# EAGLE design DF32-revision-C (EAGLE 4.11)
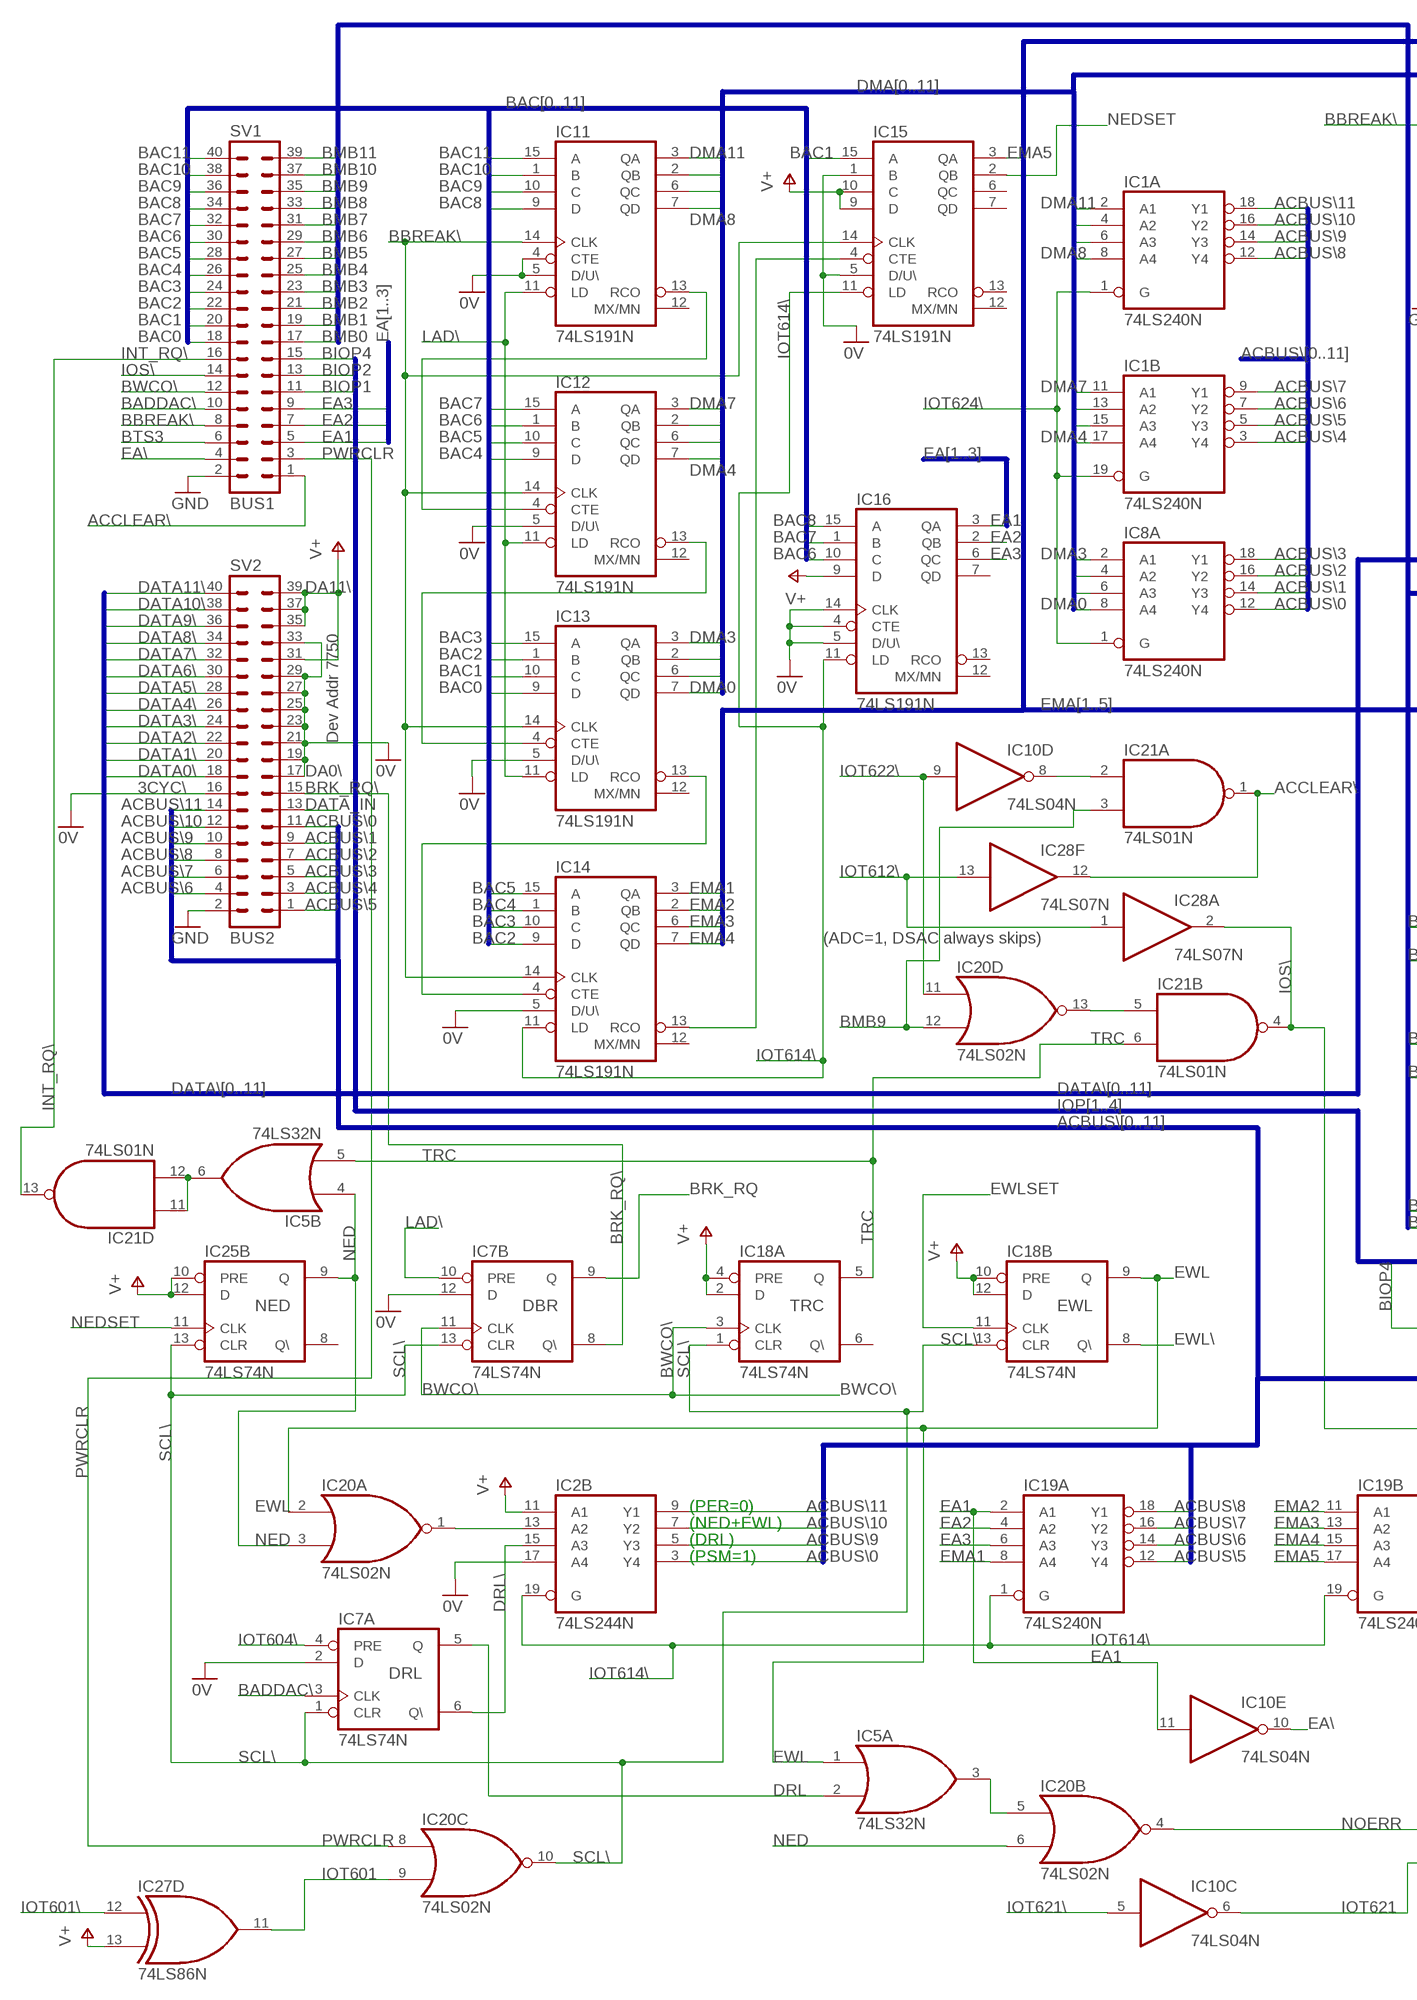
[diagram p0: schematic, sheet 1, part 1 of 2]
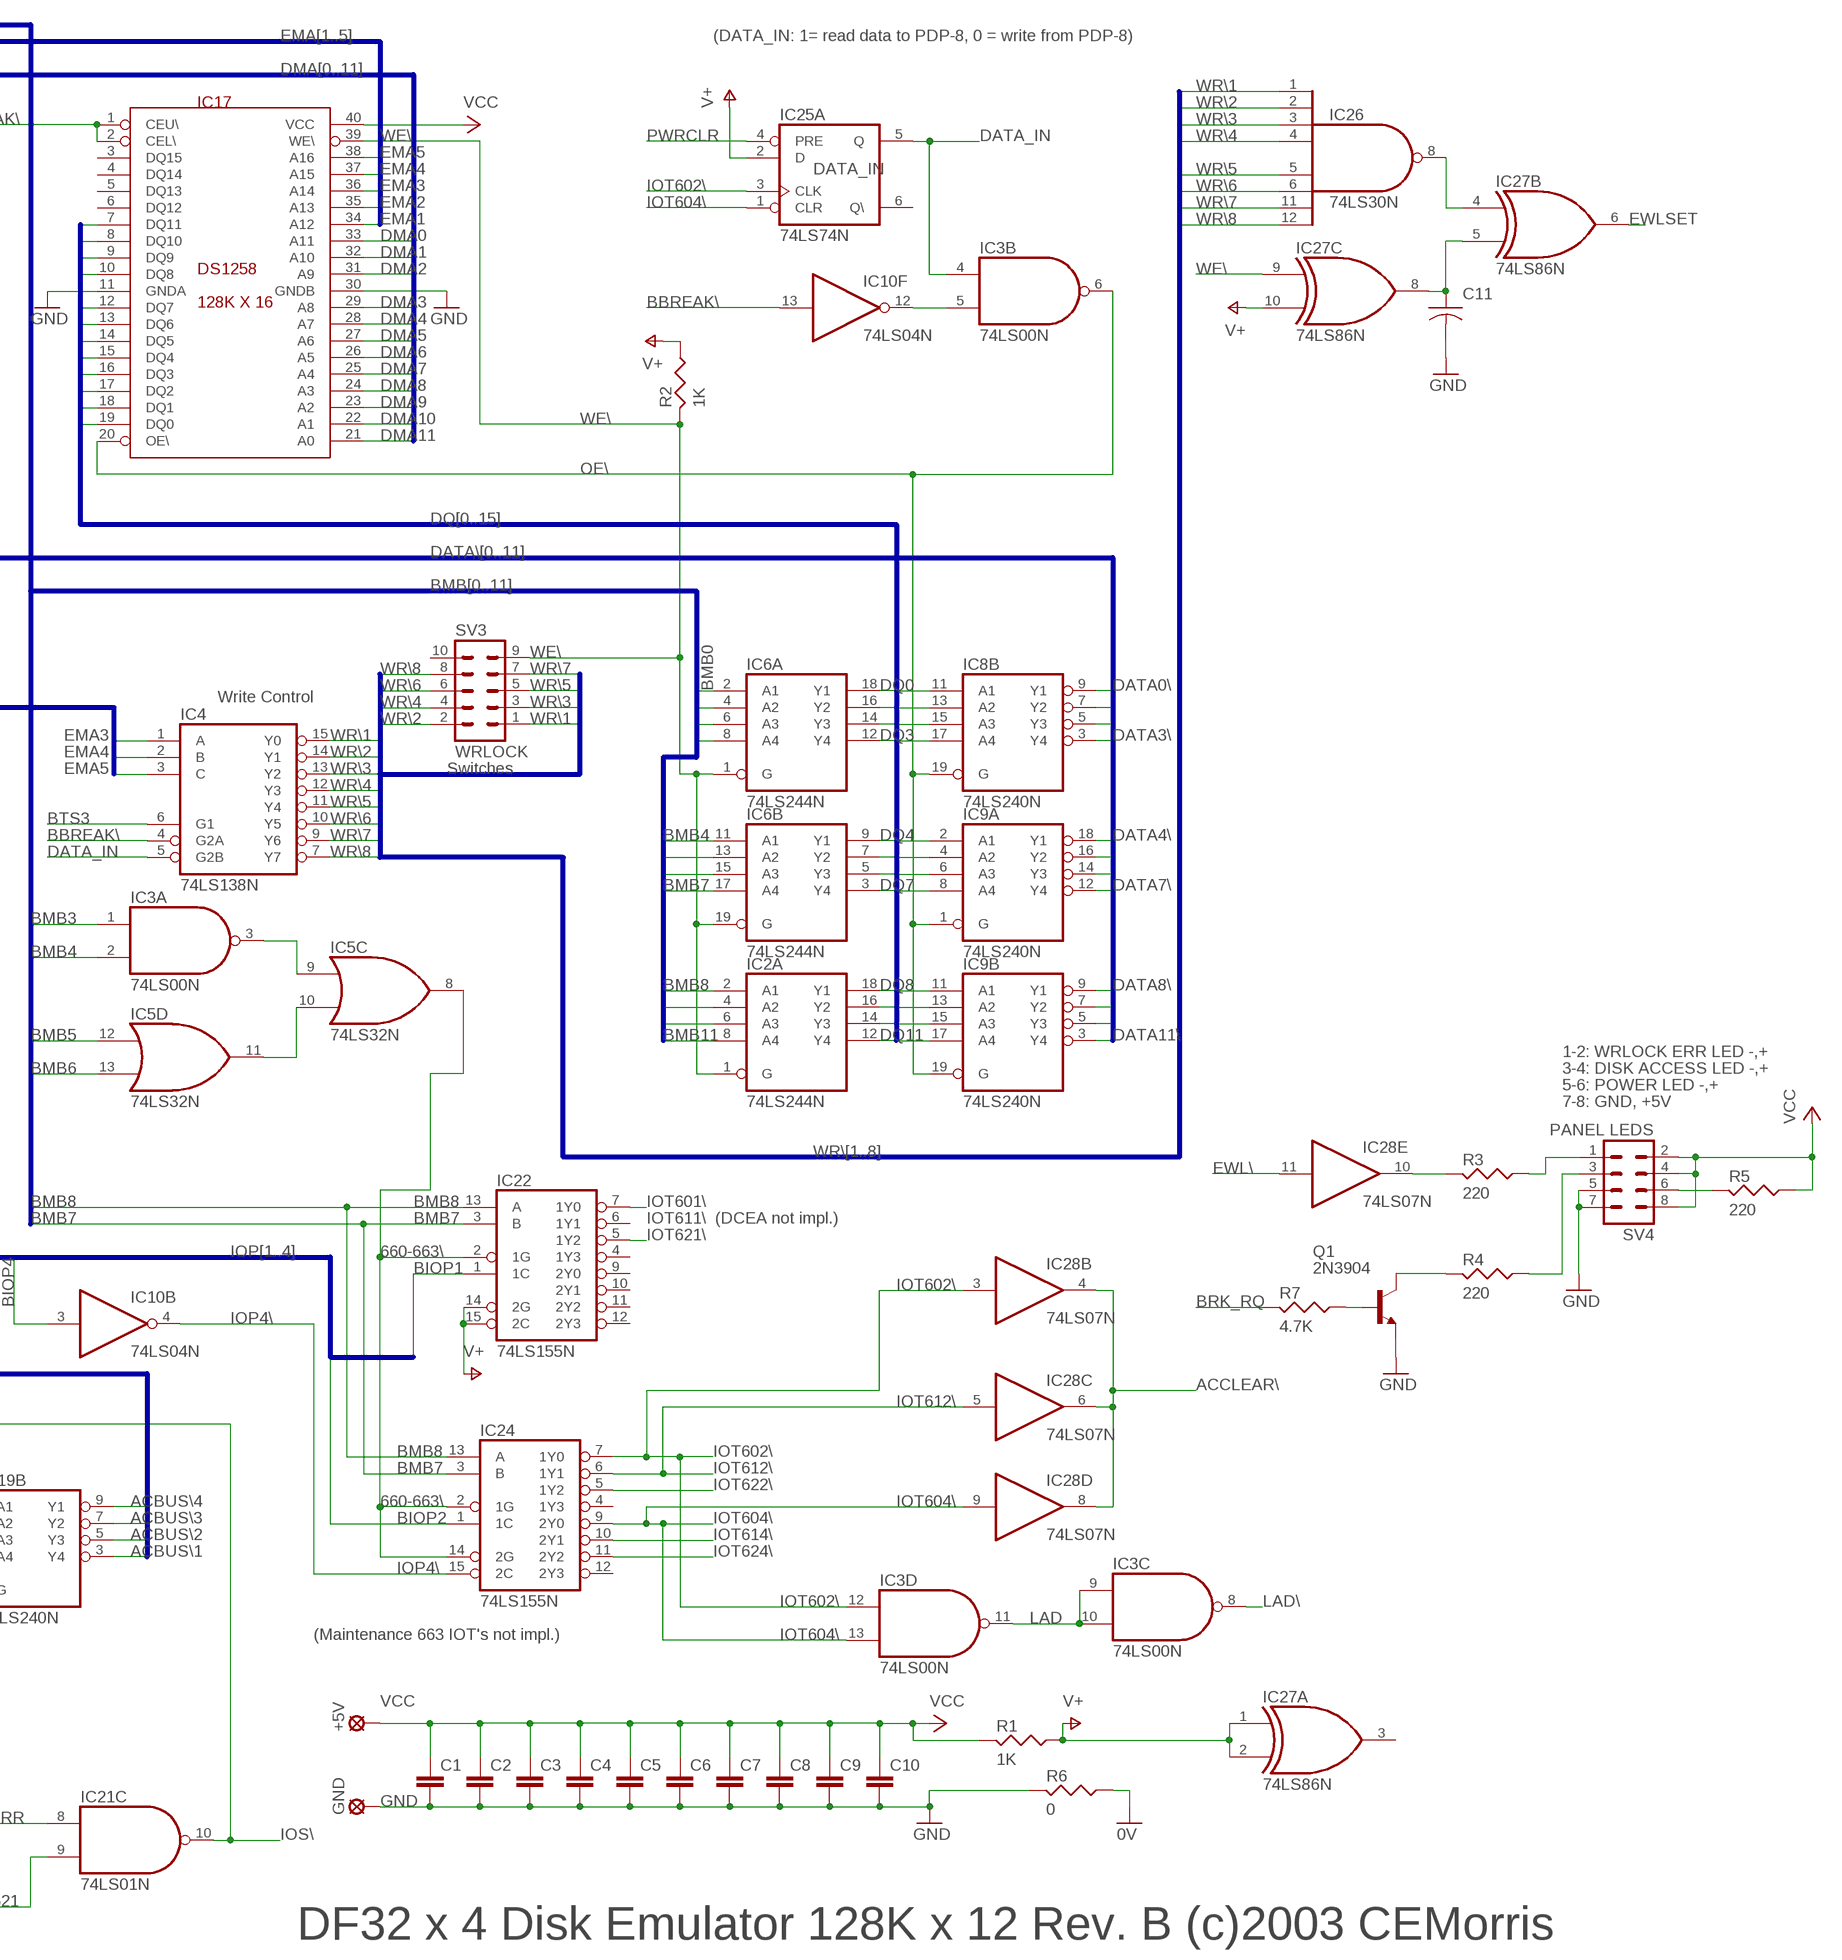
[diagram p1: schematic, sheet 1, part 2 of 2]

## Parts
+5V  SE14  [SE14]
C1  C5/3.5  [C5B3.5]
C2  C5/3.5  [C5B3.5]
C3  C5/3.5  [C5B3.5]
C4  C5/3.5  [C5B3.5]
C5  C5/3.5  [C5B3.5]
C6  C5/3.5  [C5B3.5]
C7  C5/3.5  [C5B3.5]
C8  C5/3.5  [C5B3.5]
C9  C5/3.5  [C5B3.5]
C10  C5/3.5  [C5B3.5]
C11  CAP-2,5  [C-2,5]
GND  SE14  [SE14]
IC1  74LS240N  [DIL20]
IC2  74LS244N  [DIL20]
IC3  74LS00N  [DIL14]
IC4  74LS138N  [DIL16]
IC5  74LS32N  [DIL14]
IC6  74LS244N  [DIL20]
IC7  74LS74N  [DIL14]
IC8  74LS240N  [DIL20]
IC9  74LS240N  [DIL20]
IC10  74LS04N  [DIL14]
IC11  74LS191N  74LS190N  [DIL16]
IC12  74LS191N  74LS190N  [DIL16]
IC13  74LS191N  74LS190N  [DIL16]
IC14  74LS191N  74LS190N  [DIL16]
IC15  74LS191N  74LS190N  [DIL16]
IC16  74LS191N  74LS190N  [DIL16]
IC17  DS1258  [DIL40]
IC18  74LS74N  [DIL14]
IC19  74LS240N  [DIL20]
IC20  74LS02N  [DIL14]
IC21  74LS01N  [DIL14]
IC22  74LS155N  [DIL16]
IC24  74LS155N  [DIL16]
IC25  74LS74N  [DIL14]
IC26  74LS30N  [DIL14]
IC27  74LS86N  [DIL14]
IC28  74LS07N  [DIL14]
Q1  2N3904  [TO92]
R1  1K  RESUS-5  [R-5]
R2  1K  RESUS-7,5  [R-7,5]
R3  220  RESUS-5  [R-5]
R4  220  RESUS-5  [R-5]
R5  220  RESUS-5  [R-5]
R6  0  RESUS-5  [R-5]
R7  4.7K  RESUS-5  [R-5]
SV1  BUS1  MA20-2  [MA20-2]
SV2  BUS2  MA20-2  [MA20-2]
SV3  WRLOCK  MA05-2  [MA05-2]
SV4  PANEL LEDS  MA04-2  [MA04-2]

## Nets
0V: IC2.17(B:A4) IC7.2(A:D) IC7.12(B:D) IC11.4(CTE) IC11.5(D/U\) IC12.5(D/U\) IC13.5(D/U\) IC14.5(D/U\) IC15.1(B) IC15.5(D/U\) IC16.4(CTE) IC16.5(D/U\) IC16.14(CLK) R6.1 SV2.16 SV2.17 SV2.19 SV2.21 SV2.23 SV2.25 SV2.27 SV2.29 SV2.33
660-663\: IC5.8(C:O) IC22.2(1G) IC24.2(1G) IC24.14(2G)
(NED+EWL)\: IC2.13(B:A2) IC20.1(A:O)
ACBUS\0: IC2.3(B:Y4) IC8.12(A:Y4) SV2.11
ACBUS\1: IC8.14(A:Y3) IC19.3(B:Y4) SV2.9
ACBUS\2: IC8.16(A:Y2) IC19.5(B:Y3) SV2.7
ACBUS\3: IC8.18(A:Y1) IC19.7(B:Y2) SV2.5
ACBUS\4: IC1.3(B:Y4) IC19.9(B:Y1) SV2.3
ACBUS\5: IC1.5(B:Y3) IC19.12(A:Y4) SV2.1
ACBUS\6: IC1.7(B:Y2) IC19.14(A:Y3) SV2.4
ACBUS\7: IC1.9(B:Y1) IC19.16(A:Y2) SV2.6
ACBUS\8: IC1.12(A:Y4) IC19.18(A:Y1) SV2.8
ACBUS\9: IC1.14(A:Y3) IC2.5(B:Y3) SV2.10
ACBUS\10: IC1.16(A:Y2) IC2.7(B:Y2) SV2.12
ACBUS\11: IC1.18(A:Y1) IC2.9(B:Y1) SV2.14
ACCLEAR\: IC21.1(A:O) IC28.4(B:O) IC28.6(C:O) IC28.8(D:O) IC28.12(F:O) SV1.1
BAC0: IC13.9(D) SV1.18
BAC1: IC13.10(C) IC15.15(A) SV1.20
BAC2: IC13.1(B) IC14.9(D) SV1.22
BAC3: IC13.15(A) IC14.10(C) SV1.24
BAC4: IC12.9(D) IC14.1(B) SV1.26
BAC5: IC12.10(C) IC14.15(A) SV1.28
BAC6: IC12.1(B) IC16.10(C) SV1.30
BAC7: IC12.15(A) IC16.1(B) SV1.32
BAC8: IC11.9(D) IC16.15(A) SV1.34
BAC9: IC11.10(C) SV1.36
BAC10: IC11.1(B) SV1.38
BAC11: IC11.15(A) SV1.40
BADDAC\: IC7.3(A:CLK) SV1.10
BBREAK\: IC4.4(G2A) IC10.13(F:I) IC11.14(CLK) IC12.14(CLK) IC13.14(CLK) IC14.14(CLK) IC15.14(CLK) IC17.1(CEU\) IC17.2(CEL\) SV1.8
BIOP1: IC22.1(1C) SV1.11
BIOP2: IC24.1(1C) SV1.13
BIOP4: IC10.3(B:I) SV1.15
BMB0: IC6.2(A:A1) SV1.17
BMB1: IC6.4(A:A2) SV1.19
BMB2: IC6.6(A:A3) SV1.21
BMB3: IC3.1(A:I0) IC6.8(A:A4) SV1.23
BMB4: IC3.2(A:I1) IC6.11(B:A1) SV1.25
BMB5: IC5.12(D:I0) IC6.13(B:A2) SV1.27
BMB6: IC5.13(D:I1) IC6.15(B:A3) SV1.29
BMB7: IC6.17(B:A4) IC22.3(B) IC24.3(B) SV1.31
BMB8: IC2.2(A:A1) IC22.13(A) IC24.13(A) SV1.33
BMB9: IC2.4(A:A2) IC20.12(D:I1) IC21.3(A:I1) SV1.35
BMB10: IC2.6(A:A3) SV1.37
BMB11: IC2.8(A:A4) SV1.39
BRK_RQ: IC7.9(B:Q) R7.2
BRK_RQ\: IC7.8(B:Q\) SV2.15
BTS3: IC4.6(G1) SV1.6
BWCO\: IC7.11(B:CLK) IC18.3(A:CLK) SV1.12
DATA0\: IC8.9(B:Y1) SV2.18
DATA1\: IC8.7(B:Y2) SV2.20
DATA2\: IC8.5(B:Y3) SV2.22
DATA3\: IC8.3(B:Y4) SV2.24
DATA4\: IC9.18(A:Y1) SV2.26
DATA5\: IC9.16(A:Y2) SV2.28
DATA6\: IC9.14(A:Y3) SV2.30
DATA7\: IC9.12(A:Y4) SV2.32
DATA8\: IC9.9(B:Y1) SV2.34
DATA9\: IC9.7(B:Y2) SV2.36
DATA10\: IC9.5(B:Y3) SV2.38
DATA11\: IC9.3(B:Y4) SV2.40
DATA_IN: IC3.4(B:I0) IC4.5(G2B) IC25.5(A:Q) SV2.13
DISK_LED: R4.1 SV4.3
DMA0: IC8.8(A:A4) IC13.7(QD) IC17.33(A11)
DMA1: IC8.6(A:A3) IC13.6(QC) IC17.32(A10)
DMA2: IC8.4(A:A2) IC13.2(QB) IC17.31(A9)
DMA3: IC8.2(A:A1) IC13.3(QA) IC17.29(A8)
DMA4: IC1.17(B:A4) IC12.7(QD) IC17.28(A7)
DMA5: IC1.15(B:A3) IC12.6(QC) IC17.27(A6)
DMA6: IC1.13(B:A2) IC12.2(QB) IC17.26(A5)
DMA7: IC1.11(B:A1) IC12.3(QA) IC17.25(A4)
DMA8: IC1.8(A:A4) IC11.7(QD) IC17.24(A3)
DMA9: IC1.6(A:A3) IC11.6(QC) IC17.23(A2)
DMA10: IC1.4(A:A2) IC11.2(QB) IC17.22(A1)
DMA11: IC1.2(A:A1) IC11.3(QA) IC17.21(A0)
DQ0: IC6.18(A:Y1) IC8.11(B:A1) IC17.19(DQ0)
DQ1: IC6.16(A:Y2) IC8.13(B:A2) IC17.18(DQ1)
DQ2: IC6.14(A:Y3) IC8.15(B:A3) IC17.17(DQ2)
DQ3: IC6.12(A:Y4) IC8.17(B:A4) IC17.16(DQ3)
DQ4: IC6.9(B:Y1) IC9.2(A:A1) IC17.15(DQ4)
DQ5: IC6.7(B:Y2) IC9.4(A:A2) IC17.14(DQ5)
DQ6: IC6.5(B:Y3) IC9.6(A:A3) IC17.13(DQ6)
DQ7: IC6.3(B:Y4) IC9.8(A:A4) IC17.12(DQ7)
DQ8: IC2.18(A:Y1) IC9.11(B:A1) IC17.10(DQ8)
DQ9: IC2.16(A:Y2) IC9.13(B:A2) IC17.9(DQ9)
DQ10: IC2.14(A:Y3) IC9.15(B:A3) IC17.8(DQ10)
DQ11: IC2.12(A:Y4) IC9.17(B:A4) IC17.7(DQ11)
DRL: IC5.2(A:I1) IC7.5(A:Q)
DRL\: IC2.15(B:A3) IC7.6(A:Q\)
EA1: IC10.11(E:I) IC16.3(QA) IC19.2(A:A1) SV1.5
EA2: IC16.2(QB) IC19.4(A:A2) SV1.7
EA3: IC16.6(QC) IC19.6(A:A3) SV1.9
EA\: IC10.10(E:O) SV1.4
EMA1: IC14.3(QA) IC17.34(A12) IC19.8(A:A4)
EMA2: IC14.2(QB) IC17.35(A13) IC19.11(B:A1)
EMA3: IC4.1(A) IC14.6(QC) IC17.36(A14) IC19.13(B:A2)
EMA4: IC4.2(B) IC14.7(QD) IC17.37(A15) IC19.15(B:A3)
EMA5: IC4.3(C) IC15.3(QA) IC17.38(A16) IC19.17(B:A4)
EWL: IC5.1(A:I0) IC18.9(B:Q) IC20.2(A:I0)
EWL\: IC18.8(B:Q\) IC28.11(E:I)
EWLSET: IC18.11(B:CLK) IC27.6(B:O)
GND [supply]: C1.2 C2.2 C3.2 C4.2 C5.2 C6.2 C7.2 C8.2 C9.2 C10.2 C11.2 GND.MP IC17.11(GNDA) IC17.30(GNDB) Q1.3(E) R6.2 SV1.2 SV2.2 SV4.5 SV4.7
INT_RQ\: IC21.13(D:O) SV1.16
IOP4\: IC10.4(B:O) IC24.15(2C)
IOS\: IC21.4(B:O) IC21.10(C:O) IC28.2(A:O) SV1.14
IOT601: IC20.9(C:I1) IC27.11(D:O)
IOT601\: IC22.7(1Y0) IC27.12(D:I0)
IOT602\: IC3.12(D:I0) IC24.7(1Y0) IC25.3(A:CLK) IC28.3(B:I)
IOT604\: IC3.13(D:I1) IC7.4(A:PRE) IC24.9(2Y0) IC25.1(A:CLR) IC28.9(D:I)
IOT612\: IC24.6(1Y1) IC28.1(A:I) IC28.5(C:I) IC28.13(F:I)
IOT614\: IC2.19(B:G) IC14.11(LD) IC15.11(LD) IC16.11(LD) IC19.1(A:G) IC19.19(B:G) IC24.10(2Y1)
IOT621: IC10.6(C:O) IC21.9(C:I1)
IOT621\: IC10.5(C:I) IC22.5(1Y2)
IOT622\: IC10.9(D:I) IC20.11(D:I0) IC24.5(1Y2)
IOT624\: IC1.1(A:G) IC1.19(B:G) IC8.1(A:G) IC24.11(2Y2)
LAD: IC3.9(C:I0) IC3.10(C:I1) IC3.11(D:O)
LAD\: IC3.8(C:O) IC7.10(B:PRE) IC11.11(LD) IC12.11(LD) IC13.11(LD)
N$1: C11.1 IC27.5(B:I1) IC27.8(C:O)
N$2: IC5.6(B:O) IC21.11(D:I0) IC21.12(D:I1)
N$3: IC28.10(E:O) R3.2
N$4: IC3.5(B:I1) IC10.12(F:O)
N$5: Q1.1(C) R4.2
N$6: R5.2 SV4.6
N$10: IC13.13(RCO) IC14.4(CTE)
N$11: IC12.13(RCO) IC13.4(CTE)
N$12: IC11.13(RCO) IC12.4(CTE)
N$13: IC3.3(A:O) IC5.9(C:I0)
N$14: IC14.13(RCO) IC15.4(CTE)
N$15: IC5.10(C:I1) IC5.11(D:O)
N$17: IC20.13(D:O) IC21.5(B:I0)
N$19: IC5.3(A:O) IC20.5(B:I0)
N$21: IC10.8(D:O) IC21.2(A:I0)
N$22: IC26.8(O) IC27.4(B:I0)
N$23: Q1.2(B) R7.1
NED: IC5.4(B:I0) IC20.3(A:I1) IC20.6(B:I1) IC25.9(B:Q)
NEDSET: IC15.2(QB) IC25.11(B:CLK)
NOERR: IC20.4(B:O) IC21.8(C:I0)
OE\: IC3.6(B:O) IC8.19(B:G) IC9.1(A:G) IC9.19(B:G) IC17.20(OE\)
PWRCLR: IC20.8(C:I0) IC25.4(A:PRE) SV1.3
SCL\: IC7.1(A:CLR) IC7.13(B:CLR) IC18.1(A:CLR) IC18.13(B:CLR) IC20.10(C:O) IC25.13(B:CLR)
TRC: IC5.5(B:I1) IC18.5(A:Q) IC21.6(B:I1)
V+: IC2.11(B:A1) IC15.9(D) IC15.10(C) IC16.9(D) IC18.2(A:D) IC18.4(A:PRE) IC18.10(B:PRE) IC18.12(B:D) IC22.14(2G) IC22.15(2C) IC25.2(A:D) IC25.10(B:PRE) IC25.12(B:D) IC27.1(A:I0) IC27.2(A:I1) IC27.10(C:I1) IC27.13(D:I1) R1.1 R2.1 SV2.31 SV2.35 SV2.37 SV2.39
VCC [supply]: +5V.MP C1.1 C2.1 C3.1 C4.1 C5.1 C6.1 C7.1 C8.1 C9.1 C10.1 IC17.40(VCC) R1.2 R5.1 SV4.2 SV4.4 SV4.8
WE\: IC2.1(A:G) IC6.1(A:G) IC6.19(B:G) IC17.39(WE\) IC27.9(C:I0) R2.2 SV3.9
WR\1: IC4.15(Y0) IC26.1(I0) SV3.1
WR\2: IC4.14(Y1) IC26.2(I1) SV3.2
WR\3: IC4.13(Y2) IC26.3(I2) SV3.3
WR\4: IC4.12(Y3) IC26.4(I3) SV3.4
WR\5: IC4.11(Y4) IC26.5(I4) SV3.5
WR\6: IC4.10(Y5) IC26.6(I5) SV3.6
WR\7: IC4.9(Y6) IC26.11(I6) SV3.7
WR\8: IC4.7(Y7) IC26.12(I7) SV3.8
WRITELOCK_LED: R3.1 SV4.1
Unconnected: IC10.1(A:I) IC10.2(A:O) IC11.12(MX/MN) IC12.12(MX/MN) IC13.12(MX/MN) IC14.12(MX/MN) IC15.6(QC) IC15.7(QD) IC15.12(MX/MN) IC15.13(RCO) IC16.7(QD) IC16.12(MX/MN) IC16.13(RCO) IC17.3(DQ15) IC17.4(DQ14) IC17.5(DQ13) IC17.6(DQ12) IC18.6(A:Q\) IC22.4(1Y3) IC22.6(1Y1) IC22.9(2Y0) IC22.10(2Y1) IC22.11(2Y2) IC22.12(2Y3) IC24.4(1Y3) IC24.12(2Y3) IC25.6(A:Q\) IC25.8(B:Q\) IC27.3(A:O) SV3.10

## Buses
BAC[0..11]
DATA\[0..11]
DMA[0..11]
EMA[1..5]
BMB[0..11]
EMA[3..5]
DQ[0..15]
IOP[1..4]
ACBUS\[0..11]
EA[1..3]
WR\[1..8]

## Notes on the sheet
- (DATA_IN: 1= read data to PDP-8, 0 = write from PDP-8)
- DATA_IN
- DA11\
- Write Control
- Dev Addr 7750
- DA0\ | Switches
- 3CYC\
- (ADC=1, DSAC always skips)
- 1-2: WRLOCK ERR LED -,+
- 3-4: DISK ACCESS LED -,+
- 5-6: POWER LED -,+
- 7-8: GND, +5V
- IOT611\  (DCEA not impl.)
- NED | DBR | TRC | EWL
- (PER=0)
- (NED+EWL)
- (DRL)
- (PSM=1)
- (Maintenance 663 IOT's not impl.)
- DRL
- DF32 x 4 Disk Emulator 128K x 12 Rev. B (c)2003 CEMorris

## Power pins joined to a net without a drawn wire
GND: IC1.10(P:GND) IC2.10(P:GND) IC3.7(P:GND) IC4.8(GND) IC5.7(P:GND) IC6.10(P:GND) IC7.7(P:GND) IC8.10(P:GND) IC9.10(P:GND) IC10.7(P:GND) IC11.8(GND) IC12.8(GND) IC13.8(GND) IC14.8(GND) IC15.8(GND) IC16.8(GND) IC18.7(P:GND) IC19.10(P:GND) IC20.7(P:GND) IC21.7(P:GND) IC22.8(GND) IC24.8(GND) IC25.7(P:GND) IC26.7(GND) IC27.7(P:GND) IC28.7(P:GND)
VCC: IC1.20(P:VCC) IC2.20(P:VCC) IC3.14(P:VCC) IC4.16(VCC) IC5.14(P:VCC) IC6.20(P:VCC) IC7.14(P:VCC) IC8.20(P:VCC) IC9.20(P:VCC) IC10.14(P:VCC) IC11.16(VCC) IC12.16(VCC) IC13.16(VCC) IC14.16(VCC) IC15.16(VCC) IC16.16(VCC) IC18.14(P:VCC) IC19.20(P:VCC) IC20.14(P:VCC) IC21.14(P:VCC) IC22.16(VCC) IC24.16(VCC) IC25.14(P:VCC) IC26.14(VCC) IC27.14(P:VCC) IC28.14(P:VCC)

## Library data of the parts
+5V GND = solpad:SE14: SOLDER PAD
C1-C10 = capacitor-wima:C: CAPACITOR
C11 = discrete:CAP-2,5
IC1 IC8 IC9 IC19 = 74xx-us:74*240: Octal BUFFER and LINE DRIVER, 3-state
IC2 IC6 = 74xx-us:74*244: Octal BUFFER and LINE DRIVER, 3-state
IC3 = 74xx-us:74*00: Quad 2-input NAND gate
IC4 = 74xx-us:74*138: 3-line to 8-line DECODER/DEMULTIPLEXER
IC5 = 74xx-us:74*32: Quad 2-input OR gate
IC7 IC18 IC25 = 74xx-us:74*74: Dual D type positive edge triggered FLIP FLOP, preset and clear
IC10 = 74xx-us:74*04: Hex INVERTER
IC11-IC16 = 74xx-us:74*190: Synchronous UP/DOWN COUNTER
IC17 = maxim:DS1258: DS1258 128K x 16 NVRAM
IC20 = 74xx-us:74*02: Quad 2-input NOR gate
IC21 = 74xx-us:74*01: Quad 2-input NAND gate, open collector
IC22 IC24 = 74xx-us:74*155: Dual 2-line to 4-line data DECODER/DEMULTIPLEXER
IC26 = 74xx-us:74*30: 8-input NAND gate
IC27 = 74xx-us:74*86: Quad 2-input EXCLUSIV-OR (XOR) gate
IC28 = 74xx-us:74*07: Hex BUFFER, open collector high-voltage output
Q1 = transistor-npn:2N3904: NPN Transistor
R1 R3-R7 = discrete:RESUS-5
R2 = discrete:RESUS-7,5
SV1 SV2 = con-lstb:MA20-2: PIN HEADER
SV3 = con-lstb:MA05-2: PIN HEADER
SV4 = con-lstb:MA04-2: PIN HEADER

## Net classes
1 supply: width 0.508 mm

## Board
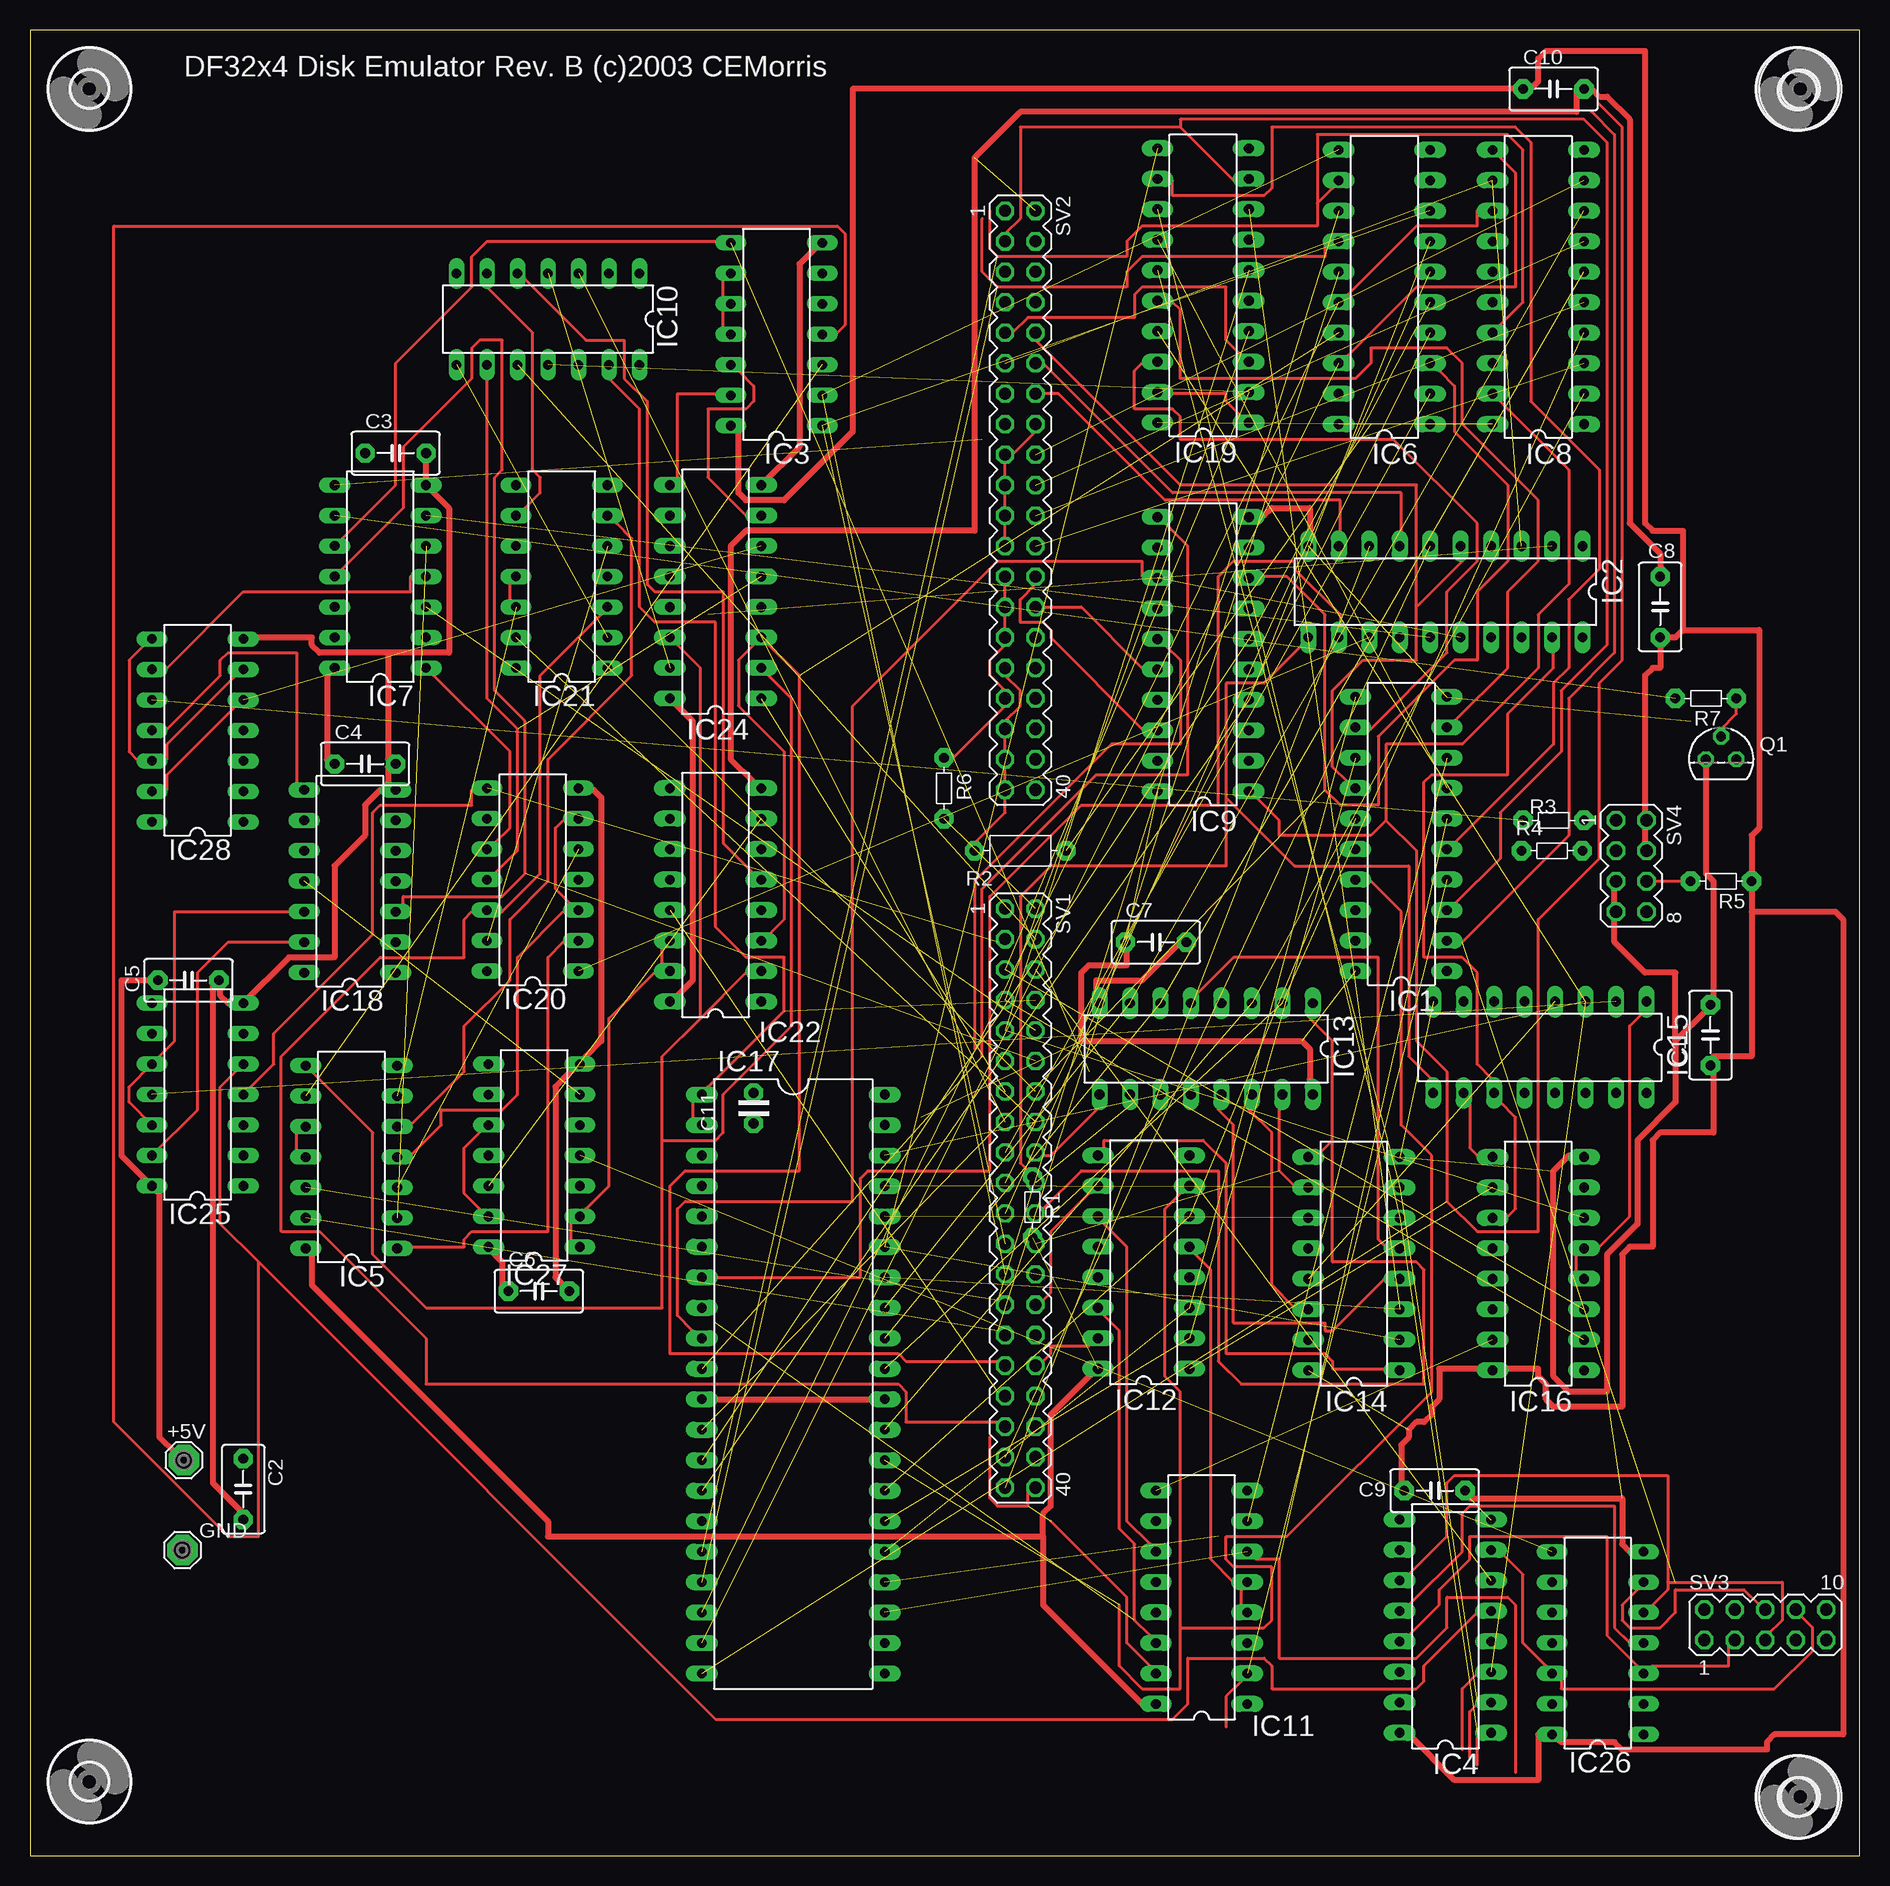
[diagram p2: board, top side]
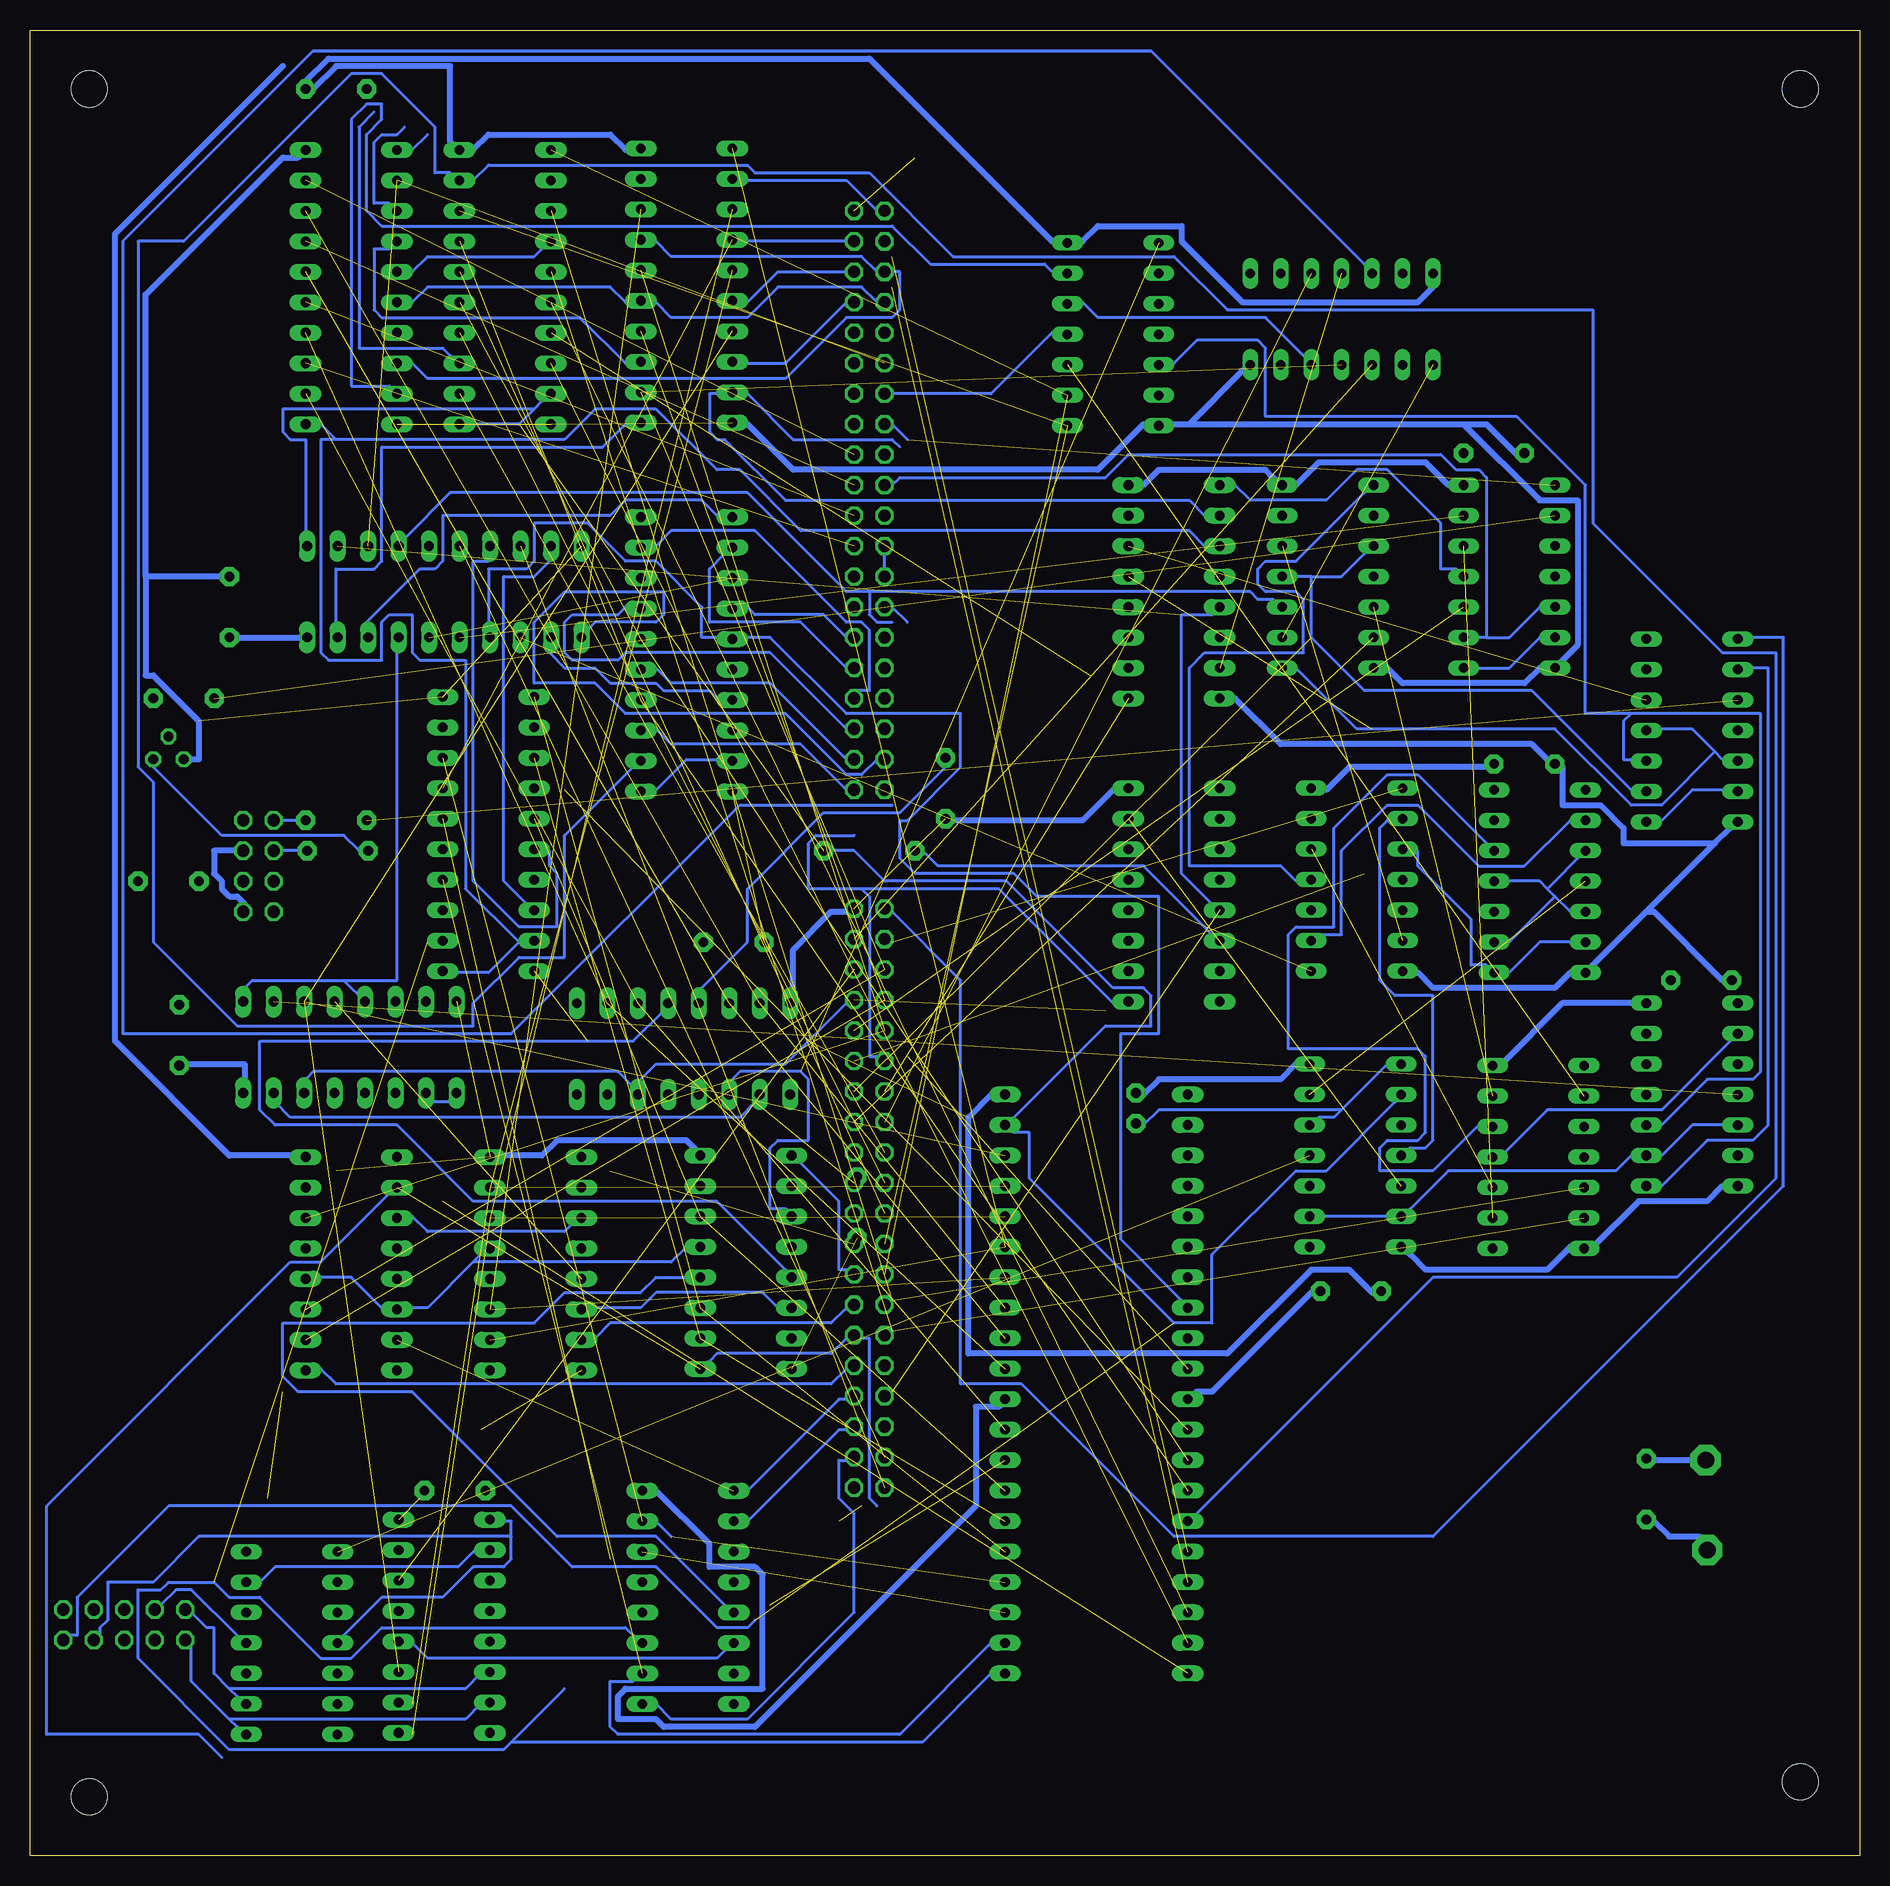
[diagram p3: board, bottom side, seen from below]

Size 152.51 x 152.2 mm. Coordinates in mm from the lower left corner, seen from the top.
Outline: 0,0 152.51,0 152.51,152.2 0,152.2 0,0
Copper layers (1*16): Top 0.035mm / dielectric 1.5mm / Bottom 0.035mm
Design rules "10mils": minimum track width 10mil, minimum drill 24mil, track to track 10mil, track to pad 10mil, pad to pad 10mil, via to via 10mil, smd to smd 10mil, copper to edge 40mil, drill to drill 10mil, minimum pad ring 10mil, minimum via ring 8mil, stop-mask expansion 0mil, vias tented up to drill 0mil, thermal gap 10mil

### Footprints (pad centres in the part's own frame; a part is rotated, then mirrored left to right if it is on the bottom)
SE14 = drill 1.397 pad 2.54 octagon: MP 0,0
C5B3.5 = drill 0.813 pad 1.6 octagon: 1 -2.54,0; 2 2.54,0
C-2,5 = drill 0.813 pad 1.6 octagon: 1 -1.27,0; 2 1.27,0
DIL20 = drill 0.813 long: 1 -11.43,-3.81; 2 -8.89,-3.81; 3 -6.35,-3.81; 4 -3.81,-3.81; 5 -1.27,-3.81; 6 1.27,-3.81; 7 3.81,-3.81; 8 6.35,-3.81; 9 8.89,-3.81; 10 11.43,-3.81; 11 11.43,3.81; 12 8.89,3.81; 13 6.35,3.81; 14 3.81,3.81; 15 1.27,3.81; 16 -1.27,3.81; 17 -3.81,3.81; 18 -6.35,3.81; 19 -8.89,3.81; 20 -11.43,3.81
DIL14 = drill 0.8 long: 1 -7.62,-3.81; 2 -5.08,-3.81; 3 -2.54,-3.81; 4 0,-3.81; 5 2.54,-3.81; 6 5.08,-3.81; 7 7.62,-3.81; 8 7.62,3.81; 9 5.08,3.81; 10 2.54,3.81; 11 0,3.81; 12 -2.54,3.81; 13 -5.08,3.81; 14 -7.62,3.81
DIL16 = drill 0.813 long: 1 -8.89,-3.81; 2 -6.35,-3.81; 3 -3.81,-3.81; 4 -1.27,-3.81; 5 1.27,-3.81; 6 3.81,-3.81; 7 6.35,-3.81; 8 8.89,-3.81; 9 8.89,3.81; 10 6.35,3.81; 11 3.81,3.81; 12 1.27,3.81; 13 -1.27,3.81; 14 -3.81,3.81; 15 -6.35,3.81; 16 -8.89,3.81
DIL40 = drill 0.813 long: 1 -24.13,-7.62; 2 -21.59,-7.62; 3 -19.05,-7.62; 4 -16.51,-7.62; 5 -13.97,-7.62; 6 -11.43,-7.62; 7 -8.89,-7.62; 8 -6.35,-7.62; 9 -3.81,-7.62; 10 -1.27,-7.62; 11 1.27,-7.62; 12 3.81,-7.62; 13 6.35,-7.62; 14 8.89,-7.62; 15 11.43,-7.62; 16 13.97,-7.62; 17 16.51,-7.62; 18 19.05,-7.62; 19 21.59,-7.62; 20 24.13,-7.62; 21 24.13,7.62; 22 21.59,7.62; 23 19.05,7.62; 24 16.51,7.62; 25 13.97,7.62; 26 11.43,7.62; 27 8.89,7.62; 28 6.35,7.62; 29 3.81,7.62; 30 1.27,7.62; 31 -1.27,7.62; 32 -3.81,7.62; 33 -6.35,7.62; 34 -8.89,7.62; 35 -11.43,7.62; 36 -13.97,7.62; 37 -16.51,7.62; 38 -19.05,7.62; 39 -21.59,7.62; 40 -24.13,7.62
TO92 = drill 0.813 octagon: 1 1.27,0; 2 0,1.905; 3 -1.27,0
R-5 = drill 0.813 pad 1.6 octagon: 1 -2.54,0; 2 2.54,0
R-7,5 = drill 0.813 pad 1.6 octagon: 1 -3.81,0; 2 3.81,0
MA20-2 = drill 1.016 octagon: 1 -24.13,-1.27; 2 -24.13,1.27; 3 -21.59,-1.27; 4 -21.59,1.27; 5 -19.05,-1.27; 6 -19.05,1.27; 7 -16.51,-1.27; 8 -16.51,1.27; 9 -13.97,-1.27; 10 -13.97,1.27; 11 -11.43,-1.27; 12 -11.43,1.27; 13 -8.89,-1.27; 14 -8.89,1.27; 15 -6.35,-1.27; 16 -6.35,1.27; 17 -3.81,-1.27; 18 -3.81,1.27; 19 -1.27,-1.27; 20 -1.27,1.27; 21 1.27,-1.27; 22 1.27,1.27; 23 3.81,-1.27; 24 3.81,1.27; 25 6.35,-1.27; 26 6.35,1.27; 27 8.89,-1.27; 28 8.89,1.27; 29 11.43,-1.27; 30 11.43,1.27; 31 13.97,-1.27; 32 13.97,1.27; 33 16.51,-1.27; 34 16.51,1.27; 35 19.05,-1.27; 36 19.05,1.27; 37 21.59,-1.27; 38 21.59,1.27; 39 24.13,-1.27; 40 24.13,1.27
MA05-2 = drill 1.016 octagon: 1 -5.08,-1.27; 2 -5.08,1.27; 3 -2.54,-1.27; 4 -2.54,1.27; 5 0,-1.27; 6 0,1.27; 7 2.54,-1.27; 8 2.54,1.27; 9 5.08,-1.27; 10 5.08,1.27
MA04-2 = drill 1.016 octagon: 1 -3.81,-1.27; 2 -3.81,1.27; 3 -1.27,-1.27; 4 -1.27,1.27; 5 1.27,-1.27; 6 1.27,1.27; 7 3.81,-1.27; 8 3.81,1.27
3,0 = hole 3: 0,0

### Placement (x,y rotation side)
+5V  12.82,32.98 0 top
C1  140.08,68.42 90 top
C2  17.78,30.57 270 top
C3  30.48,116.93 0 top
C4  27.94,91.02 0 top
C5  13.2,72.99 0 top
C6  42.41,47.08 0 top
C7  93.85,76.16 0 top
C8  135.88,104.1 90 top
C9  117.09,30.44 0 top
C10  127,147.28 0 top
C11  60.32,62.32 90 top
GND  12.69,25.49 0 top
IC1  114.3,85.18 90 top
IC2  117.98,105.37 180 top
IC3  62.22,126.84 90 top
IC4  117.98,19.14 90 top
IC5  26.79,58.26 90 top
IC6  112.9,130.77 90 top
IC7  29.21,106.64 90 top
IC8  125.73,130.77 90 top
IC9  97.79,100.17 90 top
IC10  43.17,128.1 180 top
IC11  97.66,21.55 90 top
IC12  92.83,49.49 90 top
IC13  98.04,67.27 180 top
IC14  110.36,49.37 90 top
IC15  125.85,67.4 180 top
IC16  125.73,49.37 90 top
IC17  63.62,39.33 270 top
IC18  26.67,81.24 90 top
IC19  97.79,130.9 90 top
IC20  41.9,81.37 90 top
IC21  44.32,106.64 90 top
IC22  57.14,80.1 90 top
IC24  57.14,105.37 90 top
IC25  13.96,63.46 90 top
IC26  130.68,17.74 90 top
IC27  42.03,58.38 90 top
IC28  13.96,93.81 90 top
Q1  140.97,91.4 0 top
R1  83.56,54.06 270 top
R2  82.55,83.78 0 top
R3  127,86.32 180 top
R4  126.87,83.78 180 top
R5  140.97,81.24 180 top
R6  76.2,88.99 270 top
R7  139.69,96.48 180 top
SV1  82.55,54.83 270 top
SV2  82.55,112.99 270 top
SV3  144.65,19.27 0 top
SV4  133.47,82.51 270 top
U$1  [3,0]  4.95,147.28 0 top
U$2  [3,0]  4.95,6.18 0 top
U$3  [3,0]  147.57,4.92 0 top
U$4  [3,0]  147.57,147.28 0 top

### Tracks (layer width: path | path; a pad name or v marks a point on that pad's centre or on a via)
0V
  Top 0.254: SV2.25 SV2.27 SV2.29 81.28,100.93 80.01,99.66 80.01,98.39 81.28,97.12 SV2.33 81.28,95.85 76.83,91.4 R6.1 | SV2.23 SV2.21 SV2.19 SV2.17 81.91,116.8 83.81,118.71 SV2.16 | IC11.4 100.96,20.92 100.96,22.19 IC11.5 100.33,22.82 98.42,24.73 98.42,48.86 97.15,50.13 IC12.5 | IC16.4 128.9,48.22 128.9,50.13 IC16.5 130.81,50.76 133.34,53.3 133.34,69.18 134.62,70.45 IC15.1 | IC13.5 97.15,71.72 100.33,74.89 112.39,74.89 112.39,51.4 113.03,50.76 IC14.5
  Bottom 0.254: IC13.5 96.52,72.35 92.7,76.16 92.7,80.61 86.36,86.96 80.01,86.96 76.2,90.77 R6.1 | SV2.25 SV2.23 | 79.37,102.83 80.64,104.1 SV2.27 | 126.36,72.99 133.98,72.99 134.62,72.35 IC15.1 | 126.36,72.99 IC15.5 | 126.36,72.99 121.92,72.99 121.92,100.29 IC2.17 | IC16.4 128.27,48.22 125.73,48.22 123.19,45.68 IC16.14 120.65,45.68 119.38,45.68 115.56,49.49 | 115.56,49.49 114.93,50.13 IC14.5 | 115.56,49.49 99.06,49.49 97.79,50.76 IC12.5 | 31.11,101.56 29.21,101.56 26.67,104.1 IC7.12 | 31.11,101.56 IC7.2 | 31.11,101.56 31.11,114.9 31.75,115.53 33.65,115.53 34.92,116.8 60.95,116.8 62.86,114.9 80.01,114.9 80.64,114.26 SV2.19
660-663\
  Top 0.254: 52.7,59.65 52.7,66.64 55.88,69.81 | 52.7,59.65 52.7,45.68 33.02,45.68 28.57,50.13 28.57,60.29 IC5.8 | 55.88,69.81 59.68,73.62 IC22.2 | 55.88,69.81 55.88,99.02 IC24.14 | 52.7,59.65 57.14,59.65 57.78,60.29 57.78,63.46 63.49,69.18 63.49,96.48 IC24.2
(NED+EWL)\  (1 unrouted)
ACBUS\0  (2 unrouted)
ACBUS\1
  Top 0.254: SV2.9 81.91,126.96 83.18,128.23 92.07,128.23 92.07,130.14 92.7,130.77 99.69,130.77 99.69,126.33 100.96,125.06 IC19.3
  Bottom 0.254: IC19.3 102.87,124.42 106.68,128.23 123.19,128.23 123.82,128.87 123.82,133.95 122.55,133.95 IC8.14
ACBUS\2
  Bottom 0.254: IC8.16 120.65,129.5 119.38,130.77 104.14,130.77 102.87,129.5 IC19.5 100.33,129.5 99.06,128.23 92.7,128.23 90.17,130.77 83.18,130.77 81.91,129.5 SV2.7
ACBUS\3
  Bottom 0.254: IC8.18 120.65,124.42 119.38,123.15 89.53,123.15 84.45,128.23 80.64,128.23 80.01,128.87 80.01,132.04 SV2.5 81.91,132.04 83.18,133.31 99.06,133.31 100.33,134.58 IC19.7
ACBUS\4
  Top 0.254: 95.88,144.11 100.33,139.66 IC19.9 | 95.88,144.11 82.55,144.11 82.55,136.49 81.28,135.22 SV2.3 | 95.88,144.11 95.88,144.74 129.53,144.74 131.44,142.84 131.44,100.93 127.63,97.12 127.63,92.04 122.55,86.96 122.55,83.15 118.74,79.34 IC1.3
ACBUS\5
  Top 0.254: IC1.5 118.74,84.42 127,92.67 127,97.75 128.27,99.02 128.27,104.74 130.81,107.28 130.81,115.53 125.09,121.25 125.09,142.84 123.82,144.11 103.5,144.11 103.5,139.03 102.87,138.39 95.25,138.39 95.25,139.66 IC19.12
  Bottom 0.254: SV2.1 81.91,137.12 84.45,139.66 92.7,139.66 IC19.12
ACBUS\6  (1 unrouted)
  Bottom 0.254: IC19.14 92.7,134.58 SV2.4
ACBUS\7
  Top 0.254: IC1.9 118.74,94.58 123.19,99.02 123.19,105.37 125.73,107.91 125.73,112.99 119.38,119.34 119.38,124.42 118.11,125.69 111.76,125.69 111.76,124.42 110.48,123.15 95.88,123.15 95.88,128.87 95.25,129.5 IC19.16
  Bottom 0.254: IC19.16 92.7,129.5 90.17,132.04 SV2.6
ACBUS\8
  Top 0.254: IC1.12 111.76,93.94 118.11,100.29 118.11,105.37 120.65,107.91 120.65,111.09 113.66,118.07 95.88,118.07 95.88,119.98 95.25,120.61 92.07,120.61 92.07,123.79 92.7,124.42 IC19.18
  Bottom 0.254: SV2.8 84.45,129.5 89.53,124.42 92.7,124.42 IC19.18
ACBUS\9
  Top 0.254: 115.56,104.1 115.56,99.66 111.12,99.66 108.58,97.12 108.58,90.77 109.85,89.5 IC1.14 | 115.56,104.1 119.38,107.91 IC2.5 | 115.56,104.1 115.56,114.26 95.88,114.26 83.81,126.33 SV2.10
ACBUS\10
  Top 0.254: SV2.12 84.45,124.42 95.25,113.63 114.3,113.63 114.3,110.45 IC2.7
  Bottom 0.254: IC1.16 109.22,83.78 109.22,82.51 108.58,81.88 108.58,77.43 111.76,77.43 115.56,81.24 115.56,107.91 114.3,107.91 IC2.7
ACBUS\11
  Top 0.254: SV2.14 85.72,121.88 94.61,112.99 109.22,112.99 109.22,110.45 IC2.9
  Bottom 0.254: IC1.18 111.12,79.34 113.03,81.24 113.03,106.64 110.48,106.64 109.22,107.91 IC2.9
ACCLEAR\
  Top 0.254: IC28.8 9.52,100.93 8.25,99.66 8.25,92.04 8.88,91.4 IC28.12 11.42,91.4 11.42,92.67 17.14,98.39 IC28.6
  Bottom 0.254: 12.06,92.04 13.96,93.94 16.51,93.94 IC28.4 | 12.06,92.04 11.42,91.4 IC28.12 | 12.06,92.04 16.51,87.59 19.05,87.59 25.39,93.94 41.9,93.94 46.98,99.02 IC21.1 | SV1.1 80.64,78.7 74.93,72.99 74.93,39.33 69.84,39.33 57.14,26.63 35.55,26.63 6.34,55.84 6.34,101.56 8.88,101.56 IC28.8
BAC0
  Top 0.254: IC13.9 88.9,62.19 85.09,58.38 84.45,58.38 SV1.18
BAC1  (1 unrouted)
  Bottom 0.254: IC13.10 92.07,62.83 93.34,61.56 130.81,61.56 132.08,62.83 IC15.15
BAC2
  Top 0.254: 108.58,59.65 107.31,58.38 IC14.9 | 108.58,59.65 108.58,67.91 106.68,69.81 IC13.1 | 108.58,59.65 108.58,49.49 115.56,49.49 116.2,48.86 116.2,39.33 100.96,39.33 99.06,41.24 99.06,57.11 87.62,57.11 84.45,53.94 SV1.22
BAC3  (1 unrouted)
  Top 0.254: IC14.10 105.41,55.84 104.14,57.11 104.14,62.19 IC13.15
BAC4
  Top 0.254: IC14.1 113.03,40.6 108.58,40.6 108.58,41.24 107.95,41.87 99.69,41.87 99.69,57.75 97.79,59.65 89.53,59.65 89.53,59.02 IC12.9
  Bottom 0.254: IC12.9 88.26,57.75 85.09,54.57 85.09,48.86 84.45,48.86 SV1.26
BAC5
  Top 0.254: IC12.10 88.26,55.21 85.09,52.03 85.09,46.95 84.45,46.32 SV1.28
  Bottom 0.254: IC14.15 105.41,43.14 104.14,44.41 85.72,44.41 84.45,45.68 SV1.28
BAC6  (1 unrouted)
  Bottom 0.254: IC12.1 95.88,41.24 95.25,41.87 85.72,41.87 84.45,43.14 SV1.30 83.18,43.14 82.55,43.14 82.55,29.81 81.91,29.17 | 136.52,8.22 138.43,10.12 151.12,10.12 151.12,29.17 130.81,49.49 128.27,49.49 122.55,55.21 IC16.10
BAC7
  Top 0.254: IC12.15 88.26,42.51 85.09,42.51 85.09,41.87 84.45,41.24 SV1.32
  Bottom 0.254: IC16.1 128.27,40.6 127,39.33 85.72,39.33 84.45,40.6 SV1.32
BAC8  (1 unrouted)
  Bottom 0.254: IC11.9 92.7,30.44 85.09,38.06 84.45,38.06 SV1.34
BAC9
  Bottom 0.254: IC11.10 92.7,27.9 85.09,35.52 84.45,35.52 SV1.36
BAC10
  Bottom 0.254: IC11.1 100.33,12.66 99.06,11.39 92.7,11.39 83.81,20.28 83.81,28.54 85.09,29.81 85.09,32.98 84.45,32.98 SV1.38
BAC11  (1 unrouted)
  Top 0.254: 85.09,27.9 91.44,21.55 91.44,17.74 93.34,15.84 IC11.15 | 80.01,34.89 80.01,29.81 80.64,29.17 83.18,29.17 83.18,30.44 SV1.40
BADDAC\  (1 unrouted)
BBREAK\  (1 unrouted)
  Top 0.254: IC13.14 101.59,62.19 103.5,60.29 103.5,47.59 105.41,45.68 IC14.14 | IC11.14 93.34,18.38 92.07,19.65 92.07,26 90.8,27.27 90.8,43.78 89.53,45.05 IC12.14 | IC10.13 48.25,123.15 50.79,120.61 50.79,104.1 52.06,102.83 57.14,102.83 57.14,77.43 59.68,74.89 62.86,74.89 62.86,70.45 56.51,64.1 IC17.1 55.24,62.83 55.24,61.56 IC17.2
  Bottom 0.254: IC11.14 94.61,17.11 95.25,16.47 119.38,16.47 120.65,17.74 IC4.4 | IC12.14 90.17,45.68 91.44,46.95 100.33,46.95 101.59,45.68 105.41,45.68 IC14.14 | IC15.14 129.53,64.73 128.9,65.37 103.5,65.37 102.23,64.1 IC13.14 101.59,64.73 100.33,66 89.53,66 84.45,71.08 SV1.8
BIOP1
  Bottom 0.254: 83.81,85.05 86.99,85.05 87.62,84.42 87.62,80.61 83.18,80.61 | 83.18,80.61 82.55,79.97 82.55,66.64 81.91,66.64 SV1.11 | 83.18,80.61 71.75,80.61 62.22,71.08 IC22.1
BIOP2  (1 unrouted)
BIOP4  (1 unrouted)
BMB0  (1 unrouted)
BMB1  (1 unrouted)
BMB2  (1 unrouted)
BMB3  (2 unrouted)
BMB4  (2 unrouted)
BMB5  (2 unrouted)
  Bottom 0.254: 80.64,46.32 SV1.27
BMB6  (2 unrouted)
  Bottom 0.254: 80.64,43.78 SV1.29
BMB7  (1 unrouted)
  Top 0.254: IC22.3 61.59,76.8 62.86,78.07 62.86,92.04 59.05,95.85 59.05,99.66 IC24.3 64.13,98.39 64.13,57.11 54.6,57.11 53.34,55.84 53.34,41.87 72.39,41.87 73.02,41.24 80.64,41.24 SV1.31
BMB8  (2 unrouted)
  Bottom 0.254: 80.64,38.7 SV1.33 | IC22.13 53.97,79.34 56.51,81.88 56.51,103.47 53.97,103.47 IC24.13
BMB9
  Top 0.254: IC21.3 47.62,103.47 42.54,98.39 42.54,81.88 39.36,78.7 IC20.12 36.82,78.7 36.19,78.07 36.19,74.89 29.21,74.89 20.95,66.64 20.95,52.03 24.12,52.03 33.02,43.14 33.02,39.33 72.39,39.33 73.02,38.7 73.02,36.16 80.64,36.16 SV1.35
  Bottom 0.254: 82.55,105.37 84.45,105.37 92.7,113.63 117.47,113.63 121.28,109.82 IC2.4 | 80.64,102.83 81.91,102.83 82.55,103.47 82.55,105.37 | SV1.35 80.64,36.16 | 82.55,105.37 50.79,105.37 50.16,104.74 48.89,104.74 IC21.3
BMB10  (1 unrouted)
BMB11  (1 unrouted)
BRK_RQ  (1 unrouted)
BRK_RQ\  (1 unrouted)
  Bottom 0.254: 79.37,118.07 80.64,119.34 SV2.15
BTS3  (1 unrouted)
BWCO\  (1 unrouted)
  Top 0.254: IC7.11 31.11,112.36 31.11,117.44 36.82,123.15 36.82,125.69 37.46,126.33 39.36,126.33 39.36,115.53 38.73,114.9 38.73,97.12 41.27,94.58 41.27,81.88 39.36,79.97 31.11,79.97 31.11,79.34 IC18.3
DATA0\  (1 unrouted)
DATA1\  (1 unrouted)
DATA2\  (1 unrouted)
DATA3\  (1 unrouted)
DATA4\
  Top 0.254: IC9.18 92.7,93.94 85.09,101.56 85.09,102.2 84.45,102.83 82.55,102.83 82.55,104.74 83.81,106.01 SV2.26
DATA5\
  Top 0.254: IC9.16 92.7,99.02 87.62,104.1 SV2.28
DATA6\
  Bottom 0.254: IC9.14 92.7,104.1 92.07,103.47 86.36,103.47 84.45,101.56 SV2.30
DATA7\
  Bottom 0.254: IC9.12 94.61,108.55 95.88,107.28 95.88,102.83 88.26,102.83 84.45,99.02 SV2.32
DATA8\
  Bottom 0.254: IC9.9 100.33,109.18 99.06,110.45 92.07,110.45 84.45,102.83 83.18,102.83 82.55,102.2 82.55,97.12 83.81,97.12 SV2.34
DATA9\
  Bottom 0.254: IC9.7 102.87,104.1 103.5,103.47 107.31,103.47 107.95,102.83 107.95,100.29 107.31,99.66 103.5,99.66 102.87,100.29 90.8,100.29 84.45,93.94 SV2.36
DATA10\
  Bottom 0.254: IC9.5 100.33,99.02 99.06,97.75 90.8,97.75 84.45,91.4 SV2.38
DATA11\
  Bottom 0.254: IC9.3 100.33,93.94 99.06,92.67 88.26,92.67 84.45,88.86 SV2.40
DATA_IN
  Top 0.254: IC4.5 120.65,20.28 116.2,15.84 116.2,14.57 115.56,13.93 103.5,13.93 103.5,15.84 102.87,16.47 96.52,16.47 96.52,12.66 95.25,11.39 57.14,11.39 19.05,49.49 | 19.05,49.49 15.87,52.67 15.87,64.1 IC25.5 | 19.05,49.49 19.05,26.63 16.51,26.63 6.98,36.16 6.98,135.85 67.31,135.85 67.94,135.22 67.94,127.6 67.31,126.96 IC3.4
  Bottom 0.254: IC3.4 67.31,126.96 72.39,121.88 80.64,121.88 SV2.13
DISK_LED
  Bottom 0.254: R4.1 SV4.3
DMA0  (2 unrouted)
DMA1  (2 unrouted)
DMA2  (2 unrouted)
DMA3  (2 unrouted)
DMA4  (1 unrouted)
  Top 0.254: 90.8,20.92 90.8,15.84 92.7,13.93 95.88,13.93 95.88,19.01 | 95.88,19.01 95.88,38.7 94.61,39.97 94.61,53.94 95.88,55.21 IC12.7 | 95.88,19.01 102.87,19.01 103.5,19.65 103.5,24.09 100.33,24.09 99.69,24.73 99.69,26.63 104.77,26.63 116.84,38.7 116.84,58.38 114.3,60.92 114.3,78.7 111.76,81.24 IC1.17
DMA5  (2 unrouted)
DMA6  (2 unrouted)
DMA7  (2 unrouted)
DMA8  (2 unrouted)
  Bottom 0.254: 99.06,26.63 100.33,27.9 IC11.7
DMA9  (2 unrouted)
  Top 0.254: 123.82,6.95 123.82,20.92 123.19,21.55 118.11,21.55 118.11,19.01 115.56,16.47 104.14,16.47 104.14,24.73 102.23,24.73 IC11.6
DMA10  (1 unrouted)
  Top 0.254: 99.69,10.76 99.69,13.3 100.96,14.57 IC11.2
  Bottom 0.254: IC17.22 72.39,17.74 80.01,10.12 103.5,10.12 104.14,10.76 104.14,14.57 102.23,14.57 IC11.2
DMA11  (1 unrouted)
  Top 0.254: 130.17,145.38 132.08,143.47 132.08,100.29 128.27,96.48 128.27,85.05 119.38,76.16 IC1.2
  Bottom 0.254: 112.39,9.49 113.03,8.85 135.88,8.85 143.5,16.47 143.5,22.19 141.6,22.19 140.97,22.82 137.16,22.82 135.88,21.55 133.34,21.55 128.27,16.47 125.73,16.47 123.19,19.01 102.87,19.01 102.23,18.38 IC11.3 | 112.39,9.49 107.95,13.93 | 112.39,9.49 78.1,9.49 72.39,15.2 IC17.21
DQ0  (1 unrouted)
  Top 0.254: IC6.18 109.85,125.06 115.56,130.77 123.82,130.77 123.82,140.3 IC8.11
  Bottom 0.254: 119.38,143.47 120.65,142.2 IC8.11
DQ1  (1 unrouted)
  Top 0.254: IC6.16 109.85,130.14 115.56,135.85 120.65,135.85 120.65,137.12 IC8.13
  Bottom 0.254: 121.28,144.11 121.92,143.47 123.19,143.47 123.82,142.84 123.82,137.76 122.55,137.76 IC8.13
DQ2  (1 unrouted)
  Top 0.254: 79.37,136.49 79.37,132.04 80.64,130.77 91.44,130.77 91.44,132.04 92.7,133.31 107.95,133.31 107.95,134.58 IC6.14
  Bottom 0.254: IC8.15 120.65,132.04 119.38,133.31 110.48,133.31 109.85,133.95 IC6.14
DQ3  (1 unrouted)
  Top 0.254: 80.01,137.12 80.01,133.95 80.64,133.31 91.44,133.31 91.44,134.58 92.7,135.85 107.31,135.85 107.31,137.76 | 107.31,137.76 108.58,139.03 IC6.12 | 107.31,137.76 107.31,143.47 123.19,143.47 124.45,142.2 124.45,129.5 IC8.17
DQ4
  Bottom 0.254: IC9.2 102.23,90.77 107.95,85.05 107.95,74.89 111.76,74.89 115.56,71.08 115.56,69.18 135.25,69.18 142.24,76.16 142.24,89.5 143.5,90.77 143.5,134.58 139.69,134.58 125.73,148.55 123.19,148.55 118.74,144.11 118.74,140.3 117.47,140.3 IC6.9 115.56,139.66 114.3,140.93 92.7,140.93 92.07,140.3 82.55,140.3 75.56,133.31 57.14,133.31 52.7,128.87 22.22,128.87 22.22,111.09 11.42,100.29 6.98,100.29 6.98,56.48 15.23,48.22 35.55,48.22 55.24,28.54 IC17.15
DQ5  (2 unrouted)
DQ6  (2 unrouted)
DQ7  (1 unrouted)
  Top 0.254: IC9.8 102.87,106.64 104.77,106.64 107.95,103.47 107.95,88.86 109.22,87.59 112.39,87.59 112.39,93.31 118.74,99.66 120.65,99.66 120.65,105.37 123.19,107.91 123.19,114.26 118.74,118.71 118.74,122.52 117.47,123.79 IC6.3
  Bottom 0.254: 123.82,145.38 125.09,144.11 125.09,125.69 118.11,125.69 117.47,125.06 IC6.3
DQ8  (1 unrouted)
  Top 0.254: 79.37,66.64 79.37,80.61 88.9,90.13 96.52,90.13 96.52,109.18 94.61,111.09 IC9.11
  Bottom 0.254: IC2.18 124.45,102.83 120.01,107.28 118.74,107.28 118.11,107.91 118.11,111.72 104.14,111.72 102.87,112.99 96.52,112.99 95.25,111.72 IC9.11
DQ9  (1 unrouted)
  Top 0.254: IC9.13 92.7,106.64 92.7,107.91 80.64,107.91 68.58,95.85 68.58,54.57 54.6,54.57 53.97,53.94 53.97,45.05 55.24,43.78 IC17.9
DQ10
  Top 0.254: 78.73,67.27 78.73,81.24 90.17,92.67 95.88,92.67 95.88,99.66 94.61,100.93 IC9.15
  Bottom 0.254: IC2.14 114.3,102.83 114.3,107.28 111.12,107.28 110.48,107.91 110.48,111.09 106.04,111.09 102.87,107.91 100.33,107.91 96.52,104.1 96.52,101.56 95.25,101.56 IC9.15 92.7,101.56 90.8,101.56 84.45,95.21 74.93,95.21 74.93,90.77 79.37,86.32 80.01,86.32 80.01,83.15 78.73,81.88 70.48,81.88 68.58,79.97 58.41,79.97 58.41,68.54 61.59,68.54 61.59,51.4 56.51,46.32 IC17.8
DQ11
  Top 0.254: IC2.12 109.22,102.83 109.22,103.47 105.41,107.28 105.41,107.91 100.33,107.91 99.06,106.64 99.06,87.59 87.62,87.59 80.01,79.97 80.01,57.11 69.84,57.11 69.21,56.48 69.21,48.22 IC17.7
  Bottom 0.254: IC9.17 95.25,96.48 95.88,97.12 99.69,97.12 100.33,97.75 104.14,97.75 105.41,99.02 107.95,99.02 109.22,100.29 IC2.12
DRL  (1 unrouted)
DRL\  (1 unrouted)
EA1  (3 unrouted)
EA2  (2 unrouted)
EA3  (2 unrouted)
EA\  (1 unrouted)
EMA1  (2 unrouted)
EMA2  (2 unrouted)
EMA3  (3 unrouted)
  Top 0.254: 120.65,7.58 120.65,10.12 IC4.1
EMA4  (3 unrouted)
  Top 0.254: 120.01,8.22 120.01,12.03 120.65,12.66 IC4.2
EMA5  (3 unrouted)
  Top 0.254: 119.38,8.85 119.38,13.93 120.65,15.2 IC4.3
EWL
  Top 0.254: IC5.1 31.75,50.76 36.19,50.76 36.19,51.4 36.82,52.03 43.17,52.03 43.17,74.89 44.45,76.16 IC20.2
  Bottom 0.254: IC18.9 24.12,86.32 27.94,82.51 31.75,82.51 36.82,87.59 39.36,87.59 43.17,83.78 43.17,76.8 45.08,76.8 IC20.2
EWL\
  Top 0.254: IC28.11 11.42,93.94 15.87,98.39 15.87,99.66 16.51,100.29 22.22,100.29 22.22,89.5 IC18.8
EWLSET  (1 unrouted)
GND  (8 unrouted)
  Top 0.508: C8.2 135.88,108.55 133.34,111.09 133.34,144.74 131.44,146.65 130.81,146.65 130.17,147.28 C10.2 128.9,147.28 128.9,145.38 82.55,145.38 78.73,141.57 78.73,110.45 59.68,110.45 58.41,109.18 58.41,91.4 60.32,89.5 IC22.8 | SV4.5 132.08,80.61 132.08,79.34 SV4.7 132.08,78.07 132.08,76.16 134.62,73.62 137.16,73.62 137.16,67.91 | 137.16,67.91 137.16,62.83 133.98,59.65 133.98,52.67 131.44,50.13 131.44,38.7 128.27,38.7 127,39.97 127,57.11 128.27,58.38 IC16.8 | 137.16,67.91 139.69,70.45 C1.2 140.33,71.72 140.33,81.24 139.69,81.88 Q1.3 | IC26.7 133.34,25.36 132.71,26 132.71,29.81 120.01,29.81 C9.2 | C7.2 95.88,76.16 92.7,72.99 88.9,72.99 88.9,72.35 IC13.8 | IC9.10 102.87,111.72 103.5,112.36 106.68,112.36 106.68,110.45 IC2.10 | IC17.11 IC17.30 | C6.2 43.81,48.22 43.81,64.1 45.08,65.37 IC27.7 46.35,66.64 47.62,67.91 47.62,88.23 46.98,88.86 IC20.7 | C2.2 17.78,28.54 15.23,31.08 15.23,72.99 C5.2 15.87,72.35 15.87,71.72 16.51,71.08 IC25.7 21.59,74.89 25.39,74.89 25.39,82.51 27.94,85.05 27.94,87.59 29.21,88.86 IC18.7 29.84,89.5 29.84,90.77 C4.2 29.84,91.4 29.84,100.29 | 29.84,100.29 24.12,100.29 23.49,100.93 23.49,101.56 19.05,101.56 IC28.7 | C3.2 IC7.7 34.92,112.36 34.92,100.29 29.84,100.29 | IC24.8 64.13,117.44 64.13,132.68 65.4,133.95 IC3.7
  Bottom 0.508: 142.87,106.64 142.87,130.14 131.44,141.57 130.17,141.57 IC8.10 | C8.2 142.87,106.64 | 142.87,106.64 142.87,98.39 142.24,98.39 138.43,94.58 138.43,91.4 Q1.3 | 131.44,149.19 145.41,135.22 145.41,67.91 135.88,58.38 130.81,58.38 IC16.8 | IC12.8 97.15,59.02 97.79,59.65 108.58,59.65 109.85,58.38 113.03,58.38 IC14.8 | IC13.8 88.9,72.35 88.9,75.53 85.72,78.7 84.45,78.7 SV1.2 | IC22.8 62.22,88.86 64.77,86.32 75.56,86.32 R6.2 | IC19.10 102.87,142.2 104.14,143.47 114.3,143.47 115.56,142.2 IC6.10 117.47,142.84 117.47,149.19 127,149.19 128.9,147.28 C10.2 129.53,147.92 127.63,149.82 82.55,149.82 67.31,134.58 IC3.7 64.77,134.58 63.49,135.85 56.51,135.85 56.51,134.58 51.43,129.5 36.82,129.5 35.55,130.77 IC10.7 | IC27.7 46.98,66 48.25,64.73 58.41,64.73 59.68,63.46 C11.2 | IC11.8 100.33,30.44 95.88,26 95.88,24.09 92.07,24.09 91.44,23.46 91.44,13.93 102.87,13.93 103.5,13.3 103.5,11.39 100.33,11.39 99.69,10.76 92.07,10.76 73.66,29.17 73.66,37.43 71.75,37.43 IC17.30 | C6.2 45.71,46.95 53.97,38.7 55.24,38.7 IC17.11 | C2.2 17.14,27.9 15.87,26.63 13.33,26.63 GND.MP | IC5.7 29.84,66 24.76,71.08 IC25.7 | IC20.7 44.45,88.86 42.54,90.77 31.11,90.77 C4.2 | IC24.8 59.68,114.26 58.41,115.53 49.52,115.53 48.89,114.9 IC21.7 46.98,114.26 45.08,116.17 36.19,116.17 34.28,114.26 IC7.7
INT_RQ\  (1 unrouted)
IOP4\  (1 unrouted)
IOS\  (1 unrouted)
  Bottom 0.254: 45.71,106.64 45.71,101.56 41.27,97.12 27.3,97.12 19.05,88.86 IC28.2 | 45.71,106.64 IC21.4 | 45.71,106.64 43.17,106.64 41.27,108.55 IC21.10
IOT601
  Bottom 0.254: IC27.11 37.46,59.02 36.19,59.02 35.55,59.65 35.55,71.72 38.73,71.72 40,72.99 40,85.69 39.36,86.32 IC20.9
IOT601\  (1 unrouted)
IOT602\
  Top 0.254: IC3.12 59.05,123.79 60.32,122.52 60.32,121.25 59.68,120.61 56.51,120.61 56.51,114.9 59.68,111.72 IC24.7
  Bottom 0.254: 19.05,95.21 8.25,95.21 8.25,65.37 8.88,64.73 12.69,64.73 16.51,60.92 IC25.3 | 19.05,95.21 19.68,94.58 19.68,91.4 19.05,91.4 IC28.3 | 19.05,95.21 22.86,95.21 22.86,114.26 28.57,119.98 49.52,119.98 49.52,125.69 50.16,126.33 55.24,126.33 57.14,124.42 IC3.12
IOT604\
  Top 0.254: IC3.13 57.14,121.88 53.97,121.88 53.97,114.9 IC24.9 | IC28.9 11.42,99.02 17.78,105.37 31.75,105.37 31.75,106.64 IC7.4
  Bottom 0.254: IC25.1 16.51,55.84 12.69,59.65 8.88,59.65 7.62,60.92 7.62,99.02 8.88,99.02 IC28.9 | IC24.9 52.06,114.26 50.79,112.99 44.45,112.99 41.9,115.53 39.36,115.53 34.92,111.09 34.92,107.28 33.65,107.28 IC7.4
IOT612\  (1 unrouted)
  Top 0.254: IC28.5 17.14,95.85 11.42,90.13 11.42,88.86 IC28.13
  Bottom 0.254: IC28.1 16.51,86.32 13.96,88.86 11.42,88.86 IC28.13
IOT614\
  Top 0.254: IC16.11 123.19,53.3 123.82,53.94 123.82,61.56 122.55,62.83 IC15.11 121.92,64.73 120.65,66 120.65,73.62 119.38,74.89 116.2,74.89 116.2,89.5 116.84,90.13 123.19,90.13 123.19,95.21 127,99.02 127,100.29 IC2.19 | IC19.19 95.25,121.88 99.69,121.88 99.69,121.25 100.96,119.98 IC19.1
  Bottom 0.254: 80.01,117.44 80.64,118.07 88.9,118.07 92.7,121.88 IC19.19 95.25,121.88 95.88,121.88 95.88,118.71 95.25,118.07 94.61,118.07 89.53,112.99 55.88,112.99 54.6,111.72 IC24.10 | IC14.11 107.31,52.67 107.95,52.03 119.38,52.03 120.65,53.3 IC16.11 | IC2.19 127,102.83 127,107.28 123.82,107.28 123.19,107.91 123.19,117.44 104.77,117.44 102.87,119.34 IC19.1
IOT621
  Top 0.254: IC10.6 38.09,130.77 41.9,126.96 41.9,115.53 42.54,114.9 42.54,113.63 41.27,112.36 IC21.9
IOT621\
  Top 0.254: IC10.5 41.27,131.41 46.35,126.33 49.52,126.33 49.52,123.15 51.43,121.25 51.43,106.01 52.06,105.37 57.78,105.37 57.78,84.42 60.32,81.88 IC22.5
  Bottom 0.254: 80.64,87.59 93.34,87.59 112.39,68.54 144.78,68.54 144.78,134.58 128.9,150.46 59.05,150.46 41.27,132.68 IC10.5
IOT622\  (1 unrouted)
  Top 0.254: IC20.11 38.73,81.88 40.63,83.78 40.63,93.94 38.09,96.48 IC10.9
IOT624\
  Bottom 0.254: 111.76,76.16 114.3,73.62 116.84,73.62 IC1.1 | 127,118.07 107.95,118.07 105.41,120.61 100.33,120.61 95.25,115.53 93.34,115.53 88.26,110.45 55.88,110.45 54.6,109.18 IC24.11 | 127,118.07 128.27,119.34 IC8.1 | 111.76,76.16 116.2,80.61 116.2,99.66 120.01,99.66 120.65,100.29 120.65,103.47 122.55,103.47 123.19,102.83 123.19,99.66 127.63,99.66 128.27,100.29 128.27,118.07 127,118.07 | 111.76,76.16 IC1.19
LAD
  Top 0.254: IC3.11 57.78,126.96 57.78,128.87 IC3.10 57.78,129.5 57.78,131.41 IC3.9
LAD\  (1 unrouted)
  Top 0.254: IC11.11 93.34,26 91.44,27.9 91.44,50.76 89.53,52.67 IC12.11 | IC7.10 30.48,114.26 30.48,124.42 36.82,130.77 36.82,133.31 38.09,134.58 57.14,134.58 IC3.8
  Bottom 0.254: IC13.11 93.98,64.73 93.34,65.37 88.26,65.37 87.62,64.73 87.62,59.65 90.17,59.65 90.8,59.02 90.8,53.94 89.53,53.94 IC12.11
N$1
  Bottom 0.254: 43.17,62.19 43.81,61.56 45.08,61.56 IC27.5 | 43.17,62.19 39.36,66 IC27.8 | 43.17,62.19 58.41,62.19 59.68,60.92 C11.1
N$2  (1 unrouted)
  Top 0.254: IC21.12 40,104.74 40,106.01 IC21.11
N$3  (1 unrouted)
N$4
  Bottom 0.254: IC10.12 46.35,125.06 49.52,128.23 63.49,128.23 64.77,129.5 IC3.5
N$5
  Bottom 0.254: Q1.1 142.24,90.77 136.52,85.05 126.36,85.05 125.09,83.78 R4.2
N$6
  Top 0.254: SV4.6 R5.2
N$10
  Top 0.254: IC14.4 113.03,48.22 108.58,43.78 107.95,43.78 107.95,44.41 100.33,44.41 100.33,60.92 99.06,62.19 IC13.13
N$11
  Bottom 0.254: IC12.13 89.53,48.86 95.25,54.57 115.56,54.57 121.92,60.92 132.08,60.92 133.34,62.19 133.34,67.91 102.23,67.91 99.69,70.45 IC13.4
N$12
  Bottom 0.254: IC11.13 94.61,20.92 100.33,26.63 108.58,26.63 120.65,38.7 130.17,38.7 131.44,39.97 131.44,44.41 110.48,44.41 107.95,46.95 101.59,46.95 100.33,48.22 IC12.4
N$13  (1 unrouted)
N$14  (1 unrouted)
N$15
  Top 0.254: IC5.11 22.22,58.38 22.22,60.29 IC5.10
N$17  (1 unrouted)
N$19  (1 unrouted)
N$21  (1 unrouted)
N$22  (1 unrouted)
N$23
  Top 0.254: Q1.2 140.97,93.94 142.24,95.21 R7.1
NED
  Top 0.254: IC20.6 44.45,86.32 43.81,85.69 43.81,80.61 45.08,79.34 IC20.3 44.45,78.7 40.63,74.89 40.63,63.46 39.36,62.19 34.28,62.19 34.28,60.92 31.75,58.38 IC5.4
  Bottom 0.254: IC5.4 29.84,58.38 26.03,62.19 16.51,62.19 IC25.9
NEDSET  (1 unrouted)
NOERR
  Bottom 0.254: IC21.8 41.27,113.63 46.98,107.91 49.52,107.91 50.16,107.28 50.16,106.01 49.52,105.37 46.98,105.37 46.35,104.74 46.35,100.29 54.6,100.29 55.88,99.02 55.88,82.51 48.25,82.51 46.98,81.24 IC20.4
OE\  (1 unrouted)
  Top 0.254: 113.03,86.32 113.03,92.67 119.38,92.67 125.73,99.02 125.73,103.47 128.27,106.01 128.27,115.53 IC8.19 | 113.03,86.32 111.76,85.05 104.14,85.05 104.14,86.32 102.23,88.23 IC9.1 | 113.03,86.32 115.56,83.78 115.56,67.91 118.11,65.37 118.11,54.57 120.65,52.03 125.73,52.03 125.73,78.07 130.81,83.15 130.81,97.75 132.71,99.66 132.71,144.11 130.81,146.01
  Bottom 0.254: IC9.1 100.33,88.86 97.79,91.4 95.25,91.4 IC9.19 | IC3.6 67.31,132.04 67.94,132.68 77.47,132.68 80.64,135.85 123.19,135.85 124.45,137.12 124.45,143.47 123.19,144.74 123.19,146.01 124.45,146.01 125.73,144.74 125.73,122.52 122.55,122.52 IC8.19
PWRCLR  (1 unrouted)
  Top 0.254: IC25.4 20.32,66 20.32,68.54 28.57,76.8 28.57,86.96 29.21,87.59 36.82,87.59 36.82,88.86 IC20.8
  Bottom 0.254: 80.64,76.16 SV1.3
SCL\
  Top 0.254: IC20.10 38.73,84.42 40,85.69 40,92.04 IC7.1 | IC25.13 13.96,62.19 13.96,73.62 16.51,76.16 IC18.13
  Bottom 0.254: IC7.13 26.67,101.56 29.21,99.02 IC7.1 | IC18.13 26.67,76.16 29.21,73.62 IC18.1 31.11,74.26 32.38,74.26 32.38,78.07 36.82,82.51 36.82,83.78 IC20.10
TRC
  Top 0.254: IC5.5 31.75,60.92 36.19,65.37 36.19,69.18 40,72.99 40,78.07 43.17,81.24 43.17,91.4 50.16,98.39 50.16,109.82 48.89,111.09 IC21.6
  Bottom 0.254: IC18.5 36.82,90.13 39.36,90.13 43.81,85.69 43.81,77.43 46.98,77.43 47.62,76.8 47.62,67.27 36.82,67.27 36.19,66.64 36.19,60.29 36.82,59.65 39.36,59.65 40,59.02 40,57.11 35.55,57.11 31.75,60.92 IC5.5
V+
  Top 0.254: 99.69,88.23 99.69,97.75 102.87,97.75 106.04,100.93 IC2.11 | 99.69,88.23 105.41,82.51 114.93,82.51 114.93,66.64 116.84,64.73 IC15.9 | IC16.9 120.65,58.38 120.01,59.02 120.01,62.83 IC15.10 | 99.69,88.23 99.69,82.51 85.09,82.51 82.55,79.97 82.55,57.75 83.18,57.11 R1.1 | SV2.31 81.28,98.39 82.55,97.12 82.55,95.85 81.28,94.58 SV2.35 SV2.37 SV2.39 81.28,86.96 78.73,84.42 R2.1 | IC22.14 52.7,76.16 52.7,74.26 IC22.15 52.06,73.62 48.25,69.81 48.25,55.84 46.35,53.94 IC27.2 45.08,52.67 45.08,51.4 IC27.1 | IC27.10 37.46,60.29 36.19,59.02 36.19,55.21 37.46,53.94 IC27.13 | IC25.12 8.25,62.83 8.25,64.1 IC25.10 12.06,67.91 12.06,78.7 IC18.12
  Bottom 0.254: IC15.9 117.47,62.83 119.38,62.83 IC15.10 | IC2.11 106.04,102.2 105.41,102.83 100.33,102.83 99.69,103.47 99.69,105.37 107.95,105.37 110.48,102.83 110.48,97.75 105.41,97.75 102.87,95.21 89.53,95.21 84.45,90.13 83.18,90.13 81.91,91.4 SV2.37 | IC27.2 IC27.13 37.46,53.94 34.28,57.11 20.32,57.11 19.05,58.38 IC25.2 16.51,58.38 13.96,60.92 IC25.12 | 26.03,80.61 26.67,81.24 IC18.4 | 25.39,79.97 26.03,80.61 | 25.39,79.97 24.12,78.7 IC18.12 | 25.39,79.97 29.21,76.16 IC18.2 | 26.03,80.61 IC18.10 | IC22.14 53.97,76.8 59.68,82.51 76.83,82.51 78.1,83.78 R2.1
VCC  (7 unrouted)
  Top 0.508: SV4.4 134.62,84.42 134.62,85.69 SV4.2 134.62,86.96 134.62,98.39 135.25,99.02 135.88,99.02 C8.1 137.16,101.56 137.79,102.2 | 137.79,102.2 137.79,110.45 135.25,110.45 134.62,111.09 134.62,150.46 126.36,150.46 125.73,149.82 125.73,147.92 125.09,147.28 C10.1 68.58,147.28 68.58,118.71 62.86,112.99 59.68,112.99 59.05,113.63 59.05,118.71 IC3.14 | C9.1 114.3,31.08 114.3,34.25 114.93,34.89 114.93,35.52 115.56,36.16 116.2,36.16 116.84,36.79 116.84,37.43 117.47,38.06 117.47,40.6 120.65,40.6 IC16.16 123.19,40.6 125.73,40.6 125.73,39.97 126.36,39.33 126.36,38.06 127,37.43 132.71,37.43 132.71,50.13 133.34,50.76 135.25,50.76 135.25,59.65 135.88,60.29 140.33,60.29 140.33,65.37 C1.1 140.33,66.64 143.5,66.64 143.5,78.7 | 143.5,78.7 150.49,78.7 151.12,78.07 151.12,10.12 145.41,10.12 144.78,9.49 144.78,8.85 132.71,8.85 132.08,9.49 127.63,9.49 IC26.14 125.73,10.12 125.73,6.31 118.74,6.31 114.93,10.12 IC4.16 | 143.5,78.7 R5.1 143.5,85.05 144.14,85.69 144.14,102.2 137.79,102.2 | IC13.16 106.68,64.73 106.68,67.27 106.04,67.91 87.62,67.91 87.62,73.62 88.26,74.26 91.44,74.26 91.44,75.53 C7.1 | IC22.16 53.97,71.72 55.24,72.99 55.24,94.58 IC24.16 | IC7.14 24.76,98.39 24.76,91.4 C4.1 | IC27.14 38.73,50.13 39.36,49.49 39.36,47.59 C6.1 | 84.45,26.63 84.45,20.92 92.7,12.66 IC11.16 | 84.45,26.63 84.45,28.54 85.09,29.17 85.09,36.79 88.26,39.97 IC12.16 | +5V.MP 12.06,33.62 10.79,34.89 10.79,55.21 IC25.14 7.62,58.38 7.62,72.99 C5.1 | 84.45,26.63 43.17,26.63 43.17,27.9 23.49,47.59 23.49,50.13 IC5.14
  Bottom 0.508: SV4.8 134.62,79.34 135.25,79.97 135.88,79.97 136.52,80.61 136.52,81.24 137.16,81.88 137.16,83.78 SV4.4 | C8.1 IC2.20 | IC15.16 134.62,64.73 134.62,66 139.69,66 C1.1 | IC21.14 39.36,99.02 38.09,97.75 27.94,97.75 26.67,99.02 IC7.14 23.49,100.93 23.49,112.99 26.67,112.99 33.02,119.34 | 12.06,84.42 10.79,85.69 IC28.14 | 12.06,84.42 17.78,78.7 | 17.78,78.7 IC18.14 24.12,73.62 25.39,72.35 35.55,72.35 36.82,73.62 IC20.14 | 17.78,78.7 17.14,78.7 11.42,72.99 C5.1 | 12.06,84.42 19.68,84.42 19.68,85.69 21.59,87.59 24.76,87.59 24.76,90.77 C4.1 26.03,91.4 27.3,92.67 48.25,92.67 52.06,96.48 IC24.16 | IC17.40 72.39,63.46 74.29,61.56 74.29,41.87 52.7,41.87 45.71,48.86 42.54,48.86 40.63,46.95 C6.1 | C2.1 17.14,32.98 +5V.MP | IC25.14 11.42,55.84 12.69,54.57 18.41,54.57 22.22,50.76 IC5.14 24.12,50.76 26.03,48.86 36.19,48.86 37.46,50.13 IC27.14 | 55.88,119.34 51.43,123.79 IC10.14 | 55.88,119.34 57.14,119.34 IC3.14 59.68,119.34 63.49,115.53 88.9,115.53 92.7,119.34 IC19.20 | 55.88,119.34 33.02,119.34 | 33.02,119.34 31.11,119.34 28.57,116.8 C3.1
WE\  (2 unrouted)
  Bottom 0.254: 92.07,19.65 92.7,19.01 95.25,19.01 100.33,24.09 107.31,24.09 112.39,29.17 140.97,29.17 148.59,21.55 148.59,18.38 149.22,18.38 SV3.9 | R2.2 83.81,83.78 81.28,81.24 71.12,81.24 62.22,72.35 59.68,72.35 59.05,71.72 59.05,69.18 62.86,69.18 70.48,61.56 IC17.39 70.48,60.29 69.21,60.29 69.21,56.48 57.14,44.41 53.97,44.41 53.97,50.13 46.98,57.11 44.45,57.11 38.73,62.83 IC27.9 | 110.48,120.61 111.76,119.34 IC6.1 | 110.48,120.61 109.85,121.25 IC6.19 | 110.48,120.61 131.44,120.61 131.44,118.71 130.81,118.07 129.53,118.07 129.53,110.45 IC2.1
WR\1
  Bottom 0.254: 135.88,11.39 139.06,14.57 139.06,17.74 SV3.1 | 135.88,11.39 135.25,10.76 IC26.1 | 135.88,11.39 116.2,11.39 114.93,12.66 IC4.15
WR\2
  Bottom 0.254: 135.88,13.93 137.16,15.2 137.16,19.01 137.79,19.01 139.06,20.28 SV3.2 | 135.88,13.93 135.25,13.3 IC26.2 | 135.88,13.93 116.2,13.93 114.93,15.2 IC4.14
WR\3
  Top 0.254: SV3.3 141.6,17.74 141.6,15.84 135.25,15.84 IC26.3 133.98,15.84 131.44,18.38 131.44,26.63 120.01,26.63 120.01,24.73 117.47,22.19 117.47,20.92 114.93,18.38 IC4.13
WR\4
  Top 0.254: IC4.12 114.93,20.92 119.38,25.36 119.38,28.54 120.01,29.17 132.08,29.17 132.08,19.01 133.34,17.74 IC26.4
  Bottom 0.254: IC26.4 135.25,18.38 139.06,22.19 140.33,22.19 141.6,20.92 SV3.4
WR\5
  Top 0.254: 136.52,22.82 136.52,22.19 135.25,20.92 IC26.5 | 136.52,22.82 146.05,22.82 146.05,19.65 144.78,18.38 SV3.5 | 136.52,22.82 136.52,31.71 118.74,31.71 118.11,31.08 118.11,26.63 114.93,23.46 IC4.11
WR\6
  Top 0.254: SV3.6 144.14,20.92 142.87,22.19 137.16,22.19 137.16,20.28 135.88,19.01 133.34,19.01 132.71,19.65 132.71,20.92 133.98,22.19 IC26.6
  Bottom 0.254: IC26.6 133.34,22.82 132.08,24.09 116.84,24.09 115.56,25.36 114.93,25.36 IC4.10
WR\7
  Bottom 0.254: 112.39,26.63 112.39,27.9 113.03,27.9 IC4.9 | 112.39,26.63 112.39,24.73 113.03,24.09 115.56,24.09 118.11,21.55 123.19,21.55 126.36,18.38 IC26.11 | 112.39,26.63 138.43,26.63 142.24,22.82 146.05,22.82 146.05,19.65 146.68,19.01 146.68,18.38 SV3.7
WR\8
  Top 0.254: IC4.7 122.55,25.36 124.45,23.46 124.45,17.74 126.36,15.84 IC26.12 127.63,14.57 127.63,13.93 145.41,13.93 148.59,17.11 148.59,19.01 147.31,20.28 SV3.8
WRITELOCK_LED
  Bottom 0.254: R3.1 SV4.1

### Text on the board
tNames: DF32x4 Disk Emulator Rev. B (c)2003 CEMorris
